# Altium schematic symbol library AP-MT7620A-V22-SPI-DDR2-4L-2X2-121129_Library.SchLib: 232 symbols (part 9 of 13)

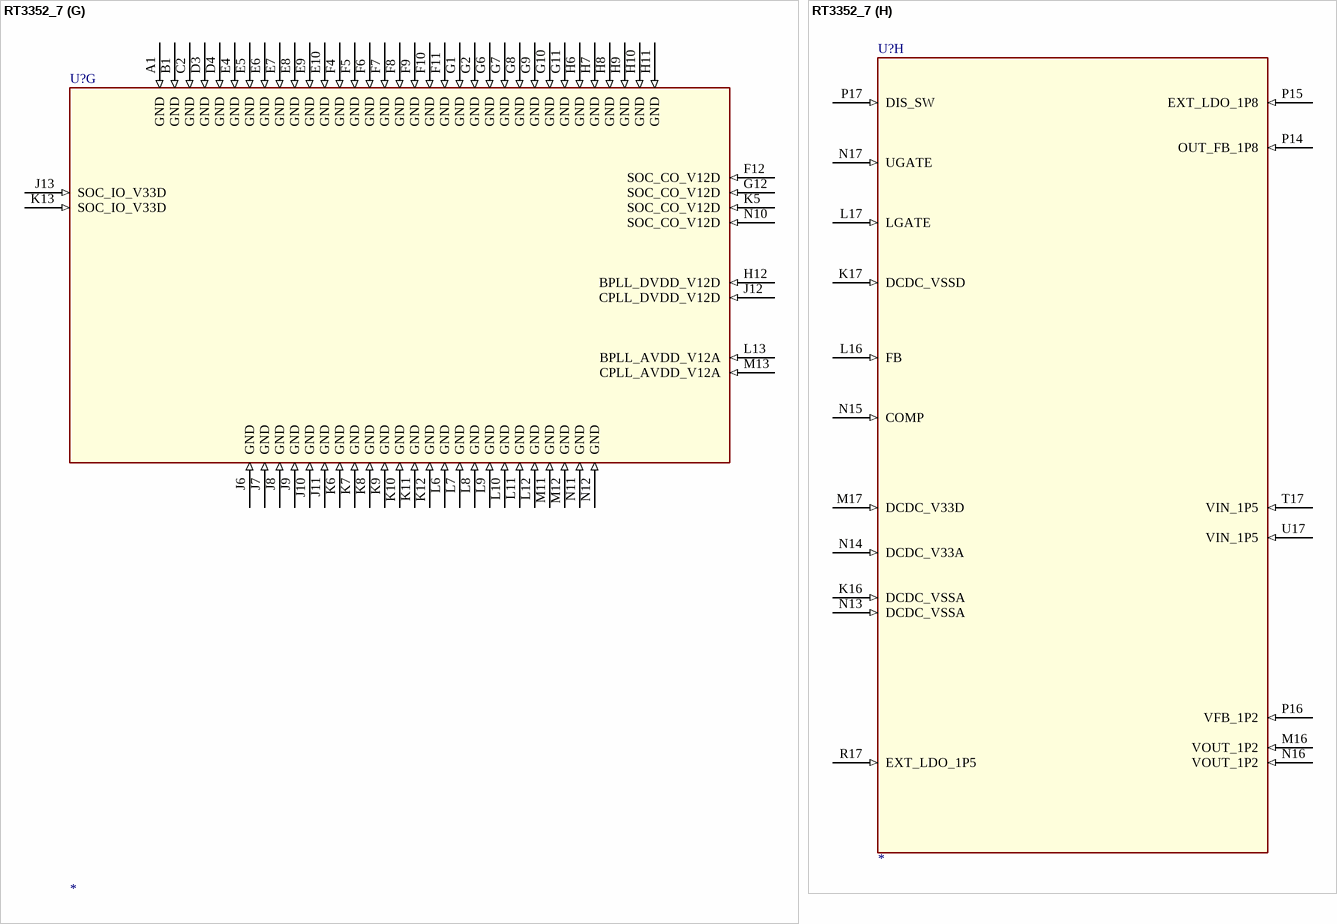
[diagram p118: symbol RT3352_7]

## RT3352_7
designator U?
part A pins: A6 PLL_VC_CAP (in), A7 LDORF_OUT_V12 (out), A8 RF_BB2_V12A (in), A9 ADC_V12 (in), B6 BG_V33A (in), B7 LDORF_IN_VX (in), B8 PLL_X2 (out), B9 PLL_X1 (in), C3 RF0_V12A (in), C4 RF0_IF_V12A (in), C5 VCO_V12A (in), C6 LDOPLL_OUT_V12 (out), C7 BG_RES_12K (in), D5 PLL_V12A (in), D6 RF_BB1_V12A (in), E3 RF1_IF_V12A (in), F3 RF1_V12A (in)
part B pins: A2 RF0_PA_OUTN (out), A3 RF0_PA_OUTP (out), A4 RF0_2G_INN (in), A5 RF0_2G_INP (in), A10 LNA_PE_G1 (out), A11 ANT_TRNB (out), B2 RF0_PA_V33N (in), B3 RF0_PA_V33P (in), B4 RF0_PA1_V33A (in), B10 LNA_PE_G0 (out), B11 ANT_TRN (out), C1 RF1_2G_INP (in), C8 BASE_TRX_IP (io), C9 BASE_TRX_IN (io), C10 PA_PE_G1 (out), D1 RF1_2G_INN (in), D2 RF1_PA_V33A (in), D7 RF_TSSI_IN (in), D8 BASE_TRX_QP (io), D9 BASE_TRX_QN (io), D10 PA_PE_G0 (out), D13 WLAN_LED_N (out), E1 RF1_PA_OUTP (out), E2 RF1_PA_V33P (in), F1 RF1_PA_OUTN (out), F2 RF1_PA_V33N (in)
part C pins: H15 MD0 (io), H16 MD1 (io), H17 MD2 (io), J12 DDR_IOC_V12D (in), J13 DDR_IOC_V12D (in), J14 MD3 (io), J15 MDQM0 (io), J16 MDQS0 (io), J17 MD6 (io), K12 DDR_IO_V33D (in), K13 DDR_IO_V33D (in), K14 MD8 (io), K15 MD7 (io), K16 MD5 (io), K17 MD4 (io), L12 DDR_IOL_V33D (in), L13 DDR_IOL_V33D (in), L14 MD13 (io), L15 MD10 (io), L16 MD11 (io), L17 MD9 (io), M11 DDR_IO_V33D (in), M12 DDR_IOR_V09D (in), M13 MD15 (io), M14 MD12 (io), M15 MD14 (io), M16 MDQS1 (io), M17 MDQM1 (io), N8 DDR_IO_V33D (in), N9 DDR_IO_V33D (in), N10 DDR_IO_V33D (in), N11 DDR_IO_V33D (in), N12 DDR_IOR_V09D (in), N13 MA0 (io), N14 MA3 (io), N15 MA8 (io), N16 MA10 (io), N17 MA13 (io), P8 MD31 (io), P9 MDQS3 (io), P10 MD22 (io), P11 MDQM2 (io), P12 MD16 (io), P13 MODT (io), P14 MA6 (io), P15 MA4 (io), P16 MA5 (io), P17 MA12 (io), R8 MD30 (io), R9 MD27 (io), R10 MD23 (io), R11 MDQS2 (io), R12 MD17 (io), R13 MCKE (io), R14 MCAS_N (io), R15 MA2 (io), R16 MA7 (io), R17 MA11 (io), T8 MD29 (io), T9 MDQM3 (io), T10 MD24 (io), T11 MD20 (io), T12 MD18 (io), T13 MCK_N (io), T14 MRAS_N (io), T15 MBA0 (io), T16 MA1 (io), T17 MA9 (io), U8 MD28 (io), U9 MD25 (io), U10 MD26 (io), U11 MD21 (io), U12 MD19 (io), U13 MCK_P (io), U14 MWE_N (io), U15 MBA1 (io), U16 MBA2 (io), U17 MCS_N (io)
part D pins: ?? NC (io), A13 JTAG_TMS (in), A14 SPI_MISO (in), A15 SPI_CS0 (out), A16 TXD (out), A17 RTS_N (out), B13 JTAG_TCLK (in), B14 SPI_MOSI (out), B15 SPI_CLK (out), B16 DTR_N (out), B17 DCD_N (in), C12 GPIO0 (io), C13 JTAG_TRST_N (in), C14 SPI_CS1 (out), C15 DSR_N (in), C16 CTS_N (in), D12 JTAG_TDO (out), D14 RIN (in), D15 RXD (in), E12 JTAG_TDI (in), E13 PORST_N (in), G15 RXD2 (in), G16 TXD2 (out), G17 I2C_SCLK (io), H14 I2C_SD (out)
part E pins: C17 UPHY1_PADP (io), D16 UPHY1_ID (io), D17 UPHY1_PADM (io), E14 UPHY_VDDL_V12D (in), E15 UPHY1_VBUS (io), E16 UPHY1_VRES (io), E17 UPHY0_PADP (io), F14 UPHY_VDDA_V33A (in), F15 UPHY0_VBUS (io), F16 UPHY0_VRES (io), F17 UPHY0_PADM (io), G14 UPHY0_ID (io)
part F pins: A12 EPHY_LED1_N (out), B12 EPHY_LED0_N (out), C11 EPHY_LED4_N (out), D11 EPHY_LED3_N (out), E11 EPHY_LED2_N (out), H3 MDC (out), H4 GE1_RXD0 (in), J3 MDIO (io), J4 GE1_RXDV (in), K3 GE1_RXD1 (in), K4 GE1_RXCLK (io), L3 GE1_RXD2 (in), L4 GE1_RXD3 (in), M3 GE1_TXD2 (out), M4 GE1_TXD3 (out), N3 GE1_TXD1 (out), N4 GE1_TXCLK (io), P3 GE1_TXD0 (out), P4 GE1_TXEN (out), P5 EPHY_V33A (in), P6 EPHY_V33A (in), P7 EPHY_V33A (in), R1 EPHY_REF_RES (io), R2 EPHY_TXN_p0 (out), R3 EPHY_RXN_p1 (in), R4 EPHY_RXN_p2 (in), R5 EPHY_RXP_p2 (in), R6 EPHY_RXP_p3 (in), R7 EPHY_RXN_p3 (in), T1 EPHY_RXN_p0 (in), T2 EPHY_TXP_p0 (out), T3 EPHY_RXP_p1 (in), T4 EPHY_TXN_p2 (out), T5 EPHY_TXN_p3 (out), T6 EPHY_RXN_p4 (in), T7 EPHY_TXN_p4 (out), U1 EPHY_RXP_p0 (in), U2 EPHY_TXP_p1 (out), U3 EPHY_TXN_p1 (out), U4 EPHY_TXP_p2 (out), U5 EPHY_TXP_p3 (out), U6 EPHY_RXP_p4 (in), U7 EPHY_TXP_p4 (out)
part G pins: A1 GND (in), B1 GND (in), C2 GND (in), D3 GND (in), D4 GND (in), E4 GND (in), E5 GND (in), E6 GND (in), E7 GND (in), E8 GND (in), E9 GND (in), E10 GND (in), F4 GND (in), F5 GND (in), F6 GND (in), F7 GND (in), F8 GND (in), F9 GND (in), F10 GND (in), F11 GND (in), F12 SOC_CO_V12D (in), G1 GND (in), G2 GND (in), G6 GND (in), G7 GND (in), G8 GND (in), G9 GND (in), G10 GND (in), G11 GND (in), G12 SOC_CO_V12D (in), H6 GND (in), H7 GND (in), H8 GND (in), H9 GND (in), H10 GND (in), H11 GND (in), H12 BPLL_DVDD_V12D (in), J6 GND (in), J7 GND (in), J8 GND (in), J9 GND (in), J10 GND (in), J11 GND (in), J12 CPLL_DVDD_V12D (in), J13 SOC_IO_V33D (in), K5 SOC_CO_V12D (in), K6 GND (in), K7 GND (in), K8 GND (in), K9 GND (in), K10 GND (in), K11 GND (in), K12 GND (in), K13 SOC_IO_V33D (in), L6 GND (in), L7 GND (in), L8 GND (in), L9 GND (in), L10 GND (in), L11 GND (in), L12 GND (in), L13 BPLL_AVDD_V12A (in), M11 GND (in), M12 GND (in), M13 CPLL_AVDD_V12A (in), N10 SOC_CO_V12D (in), N11 GND (in), N12 GND (in)
part H pins: K16 DCDC_VSSA (in), K17 DCDC_VSSD (in), L16 FB (in), L17 LGATE (in), M16 VOUT_1P2 (in), M17 DCDC_V33D (in), N13 DCDC_VSSA (in), N14 DCDC_V33A (in), N15 COMP (in), N16 VOUT_1P2 (in), N17 UGATE (in), P14 OUT_FB_1P8 (in), P15 EXT_LDO_1P8 (in), P16 VFB_1P2 (in), P17 DIS_SW (in), R17 EXT_LDO_1P5 (in), T17 VIN_1P5 (in), U17 VIN_1P5 (in)

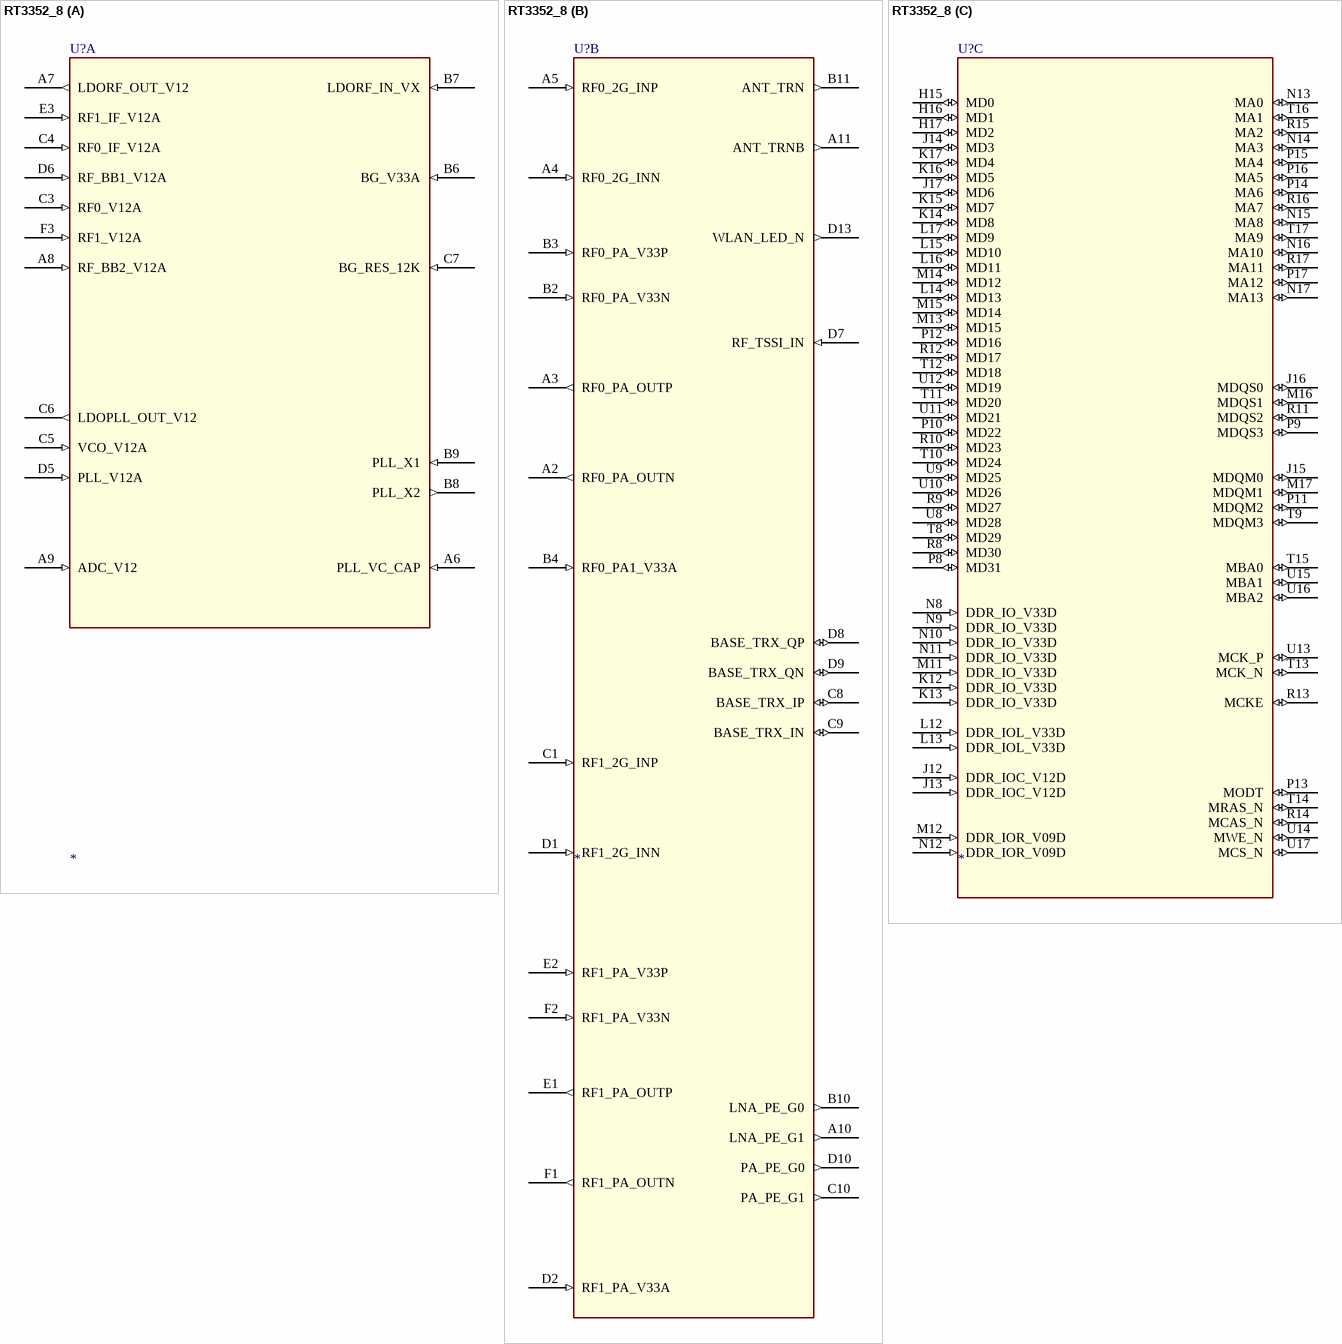
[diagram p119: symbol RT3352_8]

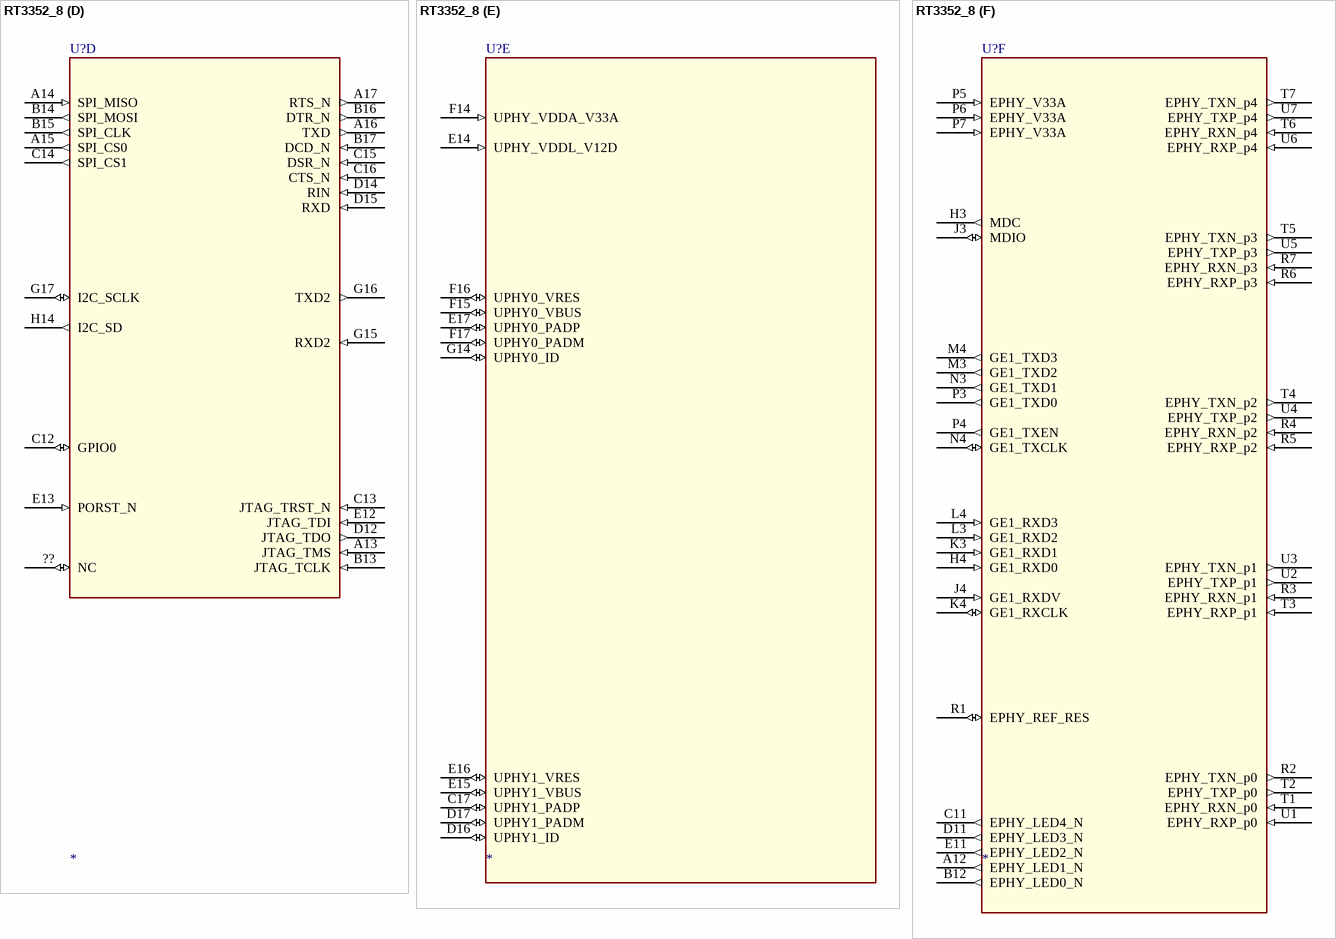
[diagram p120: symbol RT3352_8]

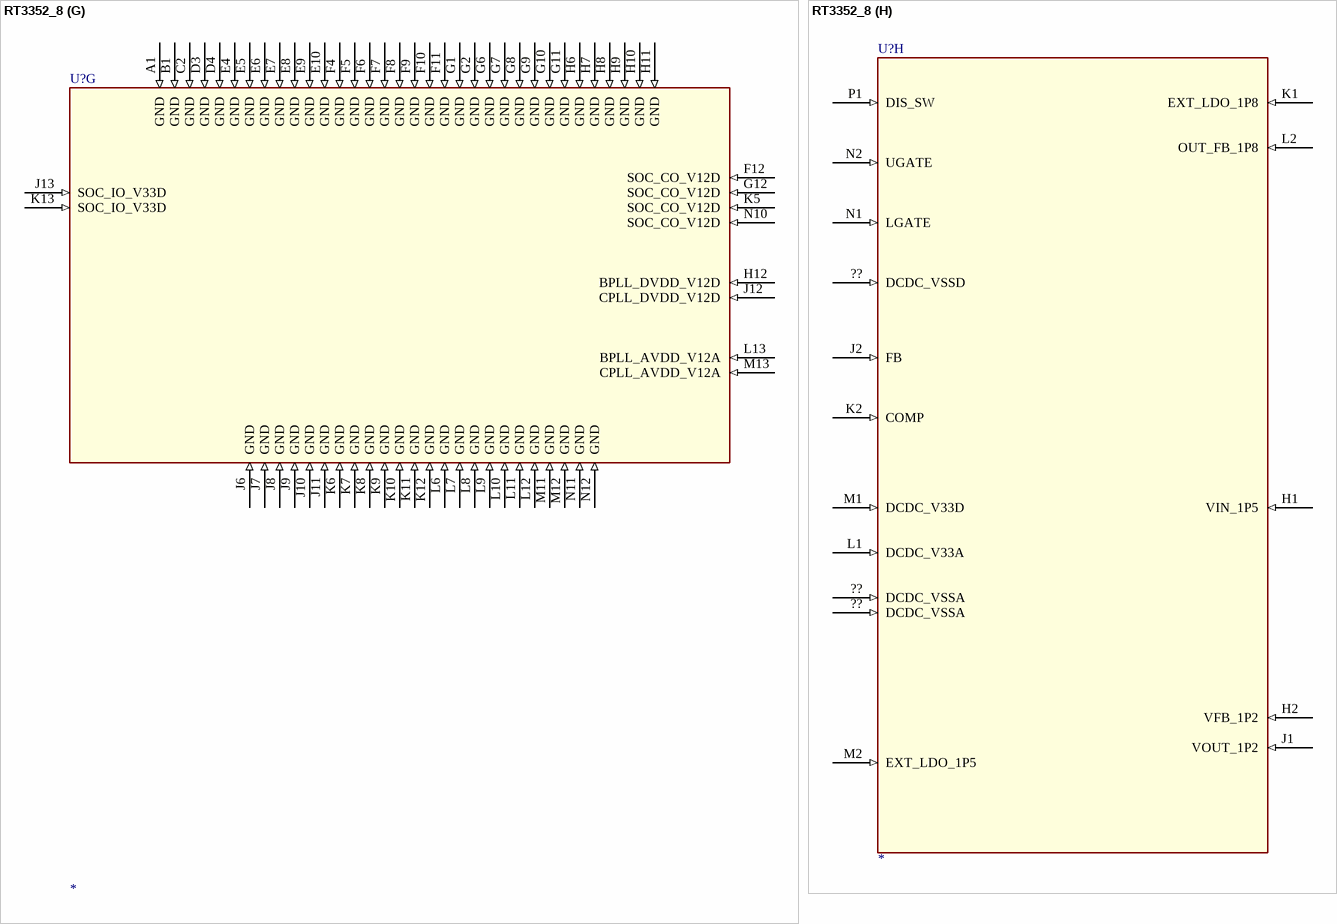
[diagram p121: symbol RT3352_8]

## RT3352_8
designator U?
part A pins: A6 PLL_VC_CAP (in), A7 LDORF_OUT_V12 (out), A8 RF_BB2_V12A (in), A9 ADC_V12 (in), B6 BG_V33A (in), B7 LDORF_IN_VX (in), B8 PLL_X2 (out), B9 PLL_X1 (in), C3 RF0_V12A (in), C4 RF0_IF_V12A (in), C5 VCO_V12A (in), C6 LDOPLL_OUT_V12 (out), C7 BG_RES_12K (in), D5 PLL_V12A (in), D6 RF_BB1_V12A (in), E3 RF1_IF_V12A (in), F3 RF1_V12A (in)
part B pins: A2 RF0_PA_OUTN (out), A3 RF0_PA_OUTP (out), A4 RF0_2G_INN (in), A5 RF0_2G_INP (in), A10 LNA_PE_G1 (out), A11 ANT_TRNB (out), B2 RF0_PA_V33N (in), B3 RF0_PA_V33P (in), B4 RF0_PA1_V33A (in), B10 LNA_PE_G0 (out), B11 ANT_TRN (out), C1 RF1_2G_INP (in), C8 BASE_TRX_IP (io), C9 BASE_TRX_IN (io), C10 PA_PE_G1 (out), D1 RF1_2G_INN (in), D2 RF1_PA_V33A (in), D7 RF_TSSI_IN (in), D8 BASE_TRX_QP (io), D9 BASE_TRX_QN (io), D10 PA_PE_G0 (out), D13 WLAN_LED_N (out), E1 RF1_PA_OUTP (out), E2 RF1_PA_V33P (in), F1 RF1_PA_OUTN (out), F2 RF1_PA_V33N (in)
part C pins: H15 MD0 (io), H16 MD1 (io), H17 MD2 (io), J12 DDR_IOC_V12D (in), J13 DDR_IOC_V12D (in), J14 MD3 (io), J15 MDQM0 (io), J16 MDQS0 (io), J17 MD6 (io), K12 DDR_IO_V33D (in), K13 DDR_IO_V33D (in), K14 MD8 (io), K15 MD7 (io), K16 MD5 (io), K17 MD4 (io), L12 DDR_IOL_V33D (in), L13 DDR_IOL_V33D (in), L14 MD13 (io), L15 MD10 (io), L16 MD11 (io), L17 MD9 (io), M11 DDR_IO_V33D (in), M12 DDR_IOR_V09D (in), M13 MD15 (io), M14 MD12 (io), M15 MD14 (io), M16 MDQS1 (io), M17 MDQM1 (io), N8 DDR_IO_V33D (in), N9 DDR_IO_V33D (in), N10 DDR_IO_V33D (in), N11 DDR_IO_V33D (in), N12 DDR_IOR_V09D (in), N13 MA0 (io), N14 MA3 (io), N15 MA8 (io), N16 MA10 (io), N17 MA13 (io), P8 MD31 (io), P9 MDQS3 (io), P10 MD22 (io), P11 MDQM2 (io), P12 MD16 (io), P13 MODT (io), P14 MA6 (io), P15 MA4 (io), P16 MA5 (io), P17 MA12 (io), R8 MD30 (io), R9 MD27 (io), R10 MD23 (io), R11 MDQS2 (io), R12 MD17 (io), R13 MCKE (io), R14 MCAS_N (io), R15 MA2 (io), R16 MA7 (io), R17 MA11 (io), T8 MD29 (io), T9 MDQM3 (io), T10 MD24 (io), T11 MD20 (io), T12 MD18 (io), T13 MCK_N (io), T14 MRAS_N (io), T15 MBA0 (io), T16 MA1 (io), T17 MA9 (io), U8 MD28 (io), U9 MD25 (io), U10 MD26 (io), U11 MD21 (io), U12 MD19 (io), U13 MCK_P (io), U14 MWE_N (io), U15 MBA1 (io), U16 MBA2 (io), U17 MCS_N (io)
part D pins: ?? NC (io), A13 JTAG_TMS (in), A14 SPI_MISO (in), A15 SPI_CS0 (out), A16 TXD (out), A17 RTS_N (out), B13 JTAG_TCLK (in), B14 SPI_MOSI (out), B15 SPI_CLK (out), B16 DTR_N (out), B17 DCD_N (in), C12 GPIO0 (io), C13 JTAG_TRST_N (in), C14 SPI_CS1 (out), C15 DSR_N (in), C16 CTS_N (in), D12 JTAG_TDO (out), D14 RIN (in), D15 RXD (in), E12 JTAG_TDI (in), E13 PORST_N (in), G15 RXD2 (in), G16 TXD2 (out), G17 I2C_SCLK (io), H14 I2C_SD (out)
part E pins: C17 UPHY1_PADP (io), D16 UPHY1_ID (io), D17 UPHY1_PADM (io), E14 UPHY_VDDL_V12D (in), E15 UPHY1_VBUS (io), E16 UPHY1_VRES (io), E17 UPHY0_PADP (io), F14 UPHY_VDDA_V33A (in), F15 UPHY0_VBUS (io), F16 UPHY0_VRES (io), F17 UPHY0_PADM (io), G14 UPHY0_ID (io)
part F pins: A12 EPHY_LED1_N (out), B12 EPHY_LED0_N (out), C11 EPHY_LED4_N (out), D11 EPHY_LED3_N (out), E11 EPHY_LED2_N (out), H3 MDC (out), H4 GE1_RXD0 (in), J3 MDIO (io), J4 GE1_RXDV (in), K3 GE1_RXD1 (in), K4 GE1_RXCLK (io), L3 GE1_RXD2 (in), L4 GE1_RXD3 (in), M3 GE1_TXD2 (out), M4 GE1_TXD3 (out), N3 GE1_TXD1 (out), N4 GE1_TXCLK (io), P3 GE1_TXD0 (out), P4 GE1_TXEN (out), P5 EPHY_V33A (in), P6 EPHY_V33A (in), P7 EPHY_V33A (in), R1 EPHY_REF_RES (io), R2 EPHY_TXN_p0 (out), R3 EPHY_RXN_p1 (in), R4 EPHY_RXN_p2 (in), R5 EPHY_RXP_p2 (in), R6 EPHY_RXP_p3 (in), R7 EPHY_RXN_p3 (in), T1 EPHY_RXN_p0 (in), T2 EPHY_TXP_p0 (out), T3 EPHY_RXP_p1 (in), T4 EPHY_TXN_p2 (out), T5 EPHY_TXN_p3 (out), T6 EPHY_RXN_p4 (in), T7 EPHY_TXN_p4 (out), U1 EPHY_RXP_p0 (in), U2 EPHY_TXP_p1 (out), U3 EPHY_TXN_p1 (out), U4 EPHY_TXP_p2 (out), U5 EPHY_TXP_p3 (out), U6 EPHY_RXP_p4 (in), U7 EPHY_TXP_p4 (out)
part G pins: A1 GND (in), B1 GND (in), C2 GND (in), D3 GND (in), D4 GND (in), E4 GND (in), E5 GND (in), E6 GND (in), E7 GND (in), E8 GND (in), E9 GND (in), E10 GND (in), F4 GND (in), F5 GND (in), F6 GND (in), F7 GND (in), F8 GND (in), F9 GND (in), F10 GND (in), F11 GND (in), F12 SOC_CO_V12D (in), G1 GND (in), G2 GND (in), G6 GND (in), G7 GND (in), G8 GND (in), G9 GND (in), G10 GND (in), G11 GND (in), G12 SOC_CO_V12D (in), H6 GND (in), H7 GND (in), H8 GND (in), H9 GND (in), H10 GND (in), H11 GND (in), H12 BPLL_DVDD_V12D (in), J6 GND (in), J7 GND (in), J8 GND (in), J9 GND (in), J10 GND (in), J11 GND (in), J12 CPLL_DVDD_V12D (in), J13 SOC_IO_V33D (in), K5 SOC_CO_V12D (in), K6 GND (in), K7 GND (in), K8 GND (in), K9 GND (in), K10 GND (in), K11 GND (in), K12 GND (in), K13 SOC_IO_V33D (in), L6 GND (in), L7 GND (in), L8 GND (in), L9 GND (in), L10 GND (in), L11 GND (in), L12 GND (in), L13 BPLL_AVDD_V12A (in), M11 GND (in), M12 GND (in), M13 CPLL_AVDD_V12A (in), N10 SOC_CO_V12D (in), N11 GND (in), N12 GND (in)
part H pins: ?? DCDC_VSSD (in), ?? DCDC_VSSA (in), ?? DCDC_VSSA (in), H1 VIN_1P5 (in), H2 VFB_1P2 (in), J1 VOUT_1P2 (in), J2 FB (in), K1 EXT_LDO_1P8 (in), K2 COMP (in), L1 DCDC_V33A (in), L2 OUT_FB_1P8 (in), M1 DCDC_V33D (in), M2 EXT_LDO_1P5 (in), N1 LGATE (in), N2 UGATE (in), P1 DIS_SW (in)

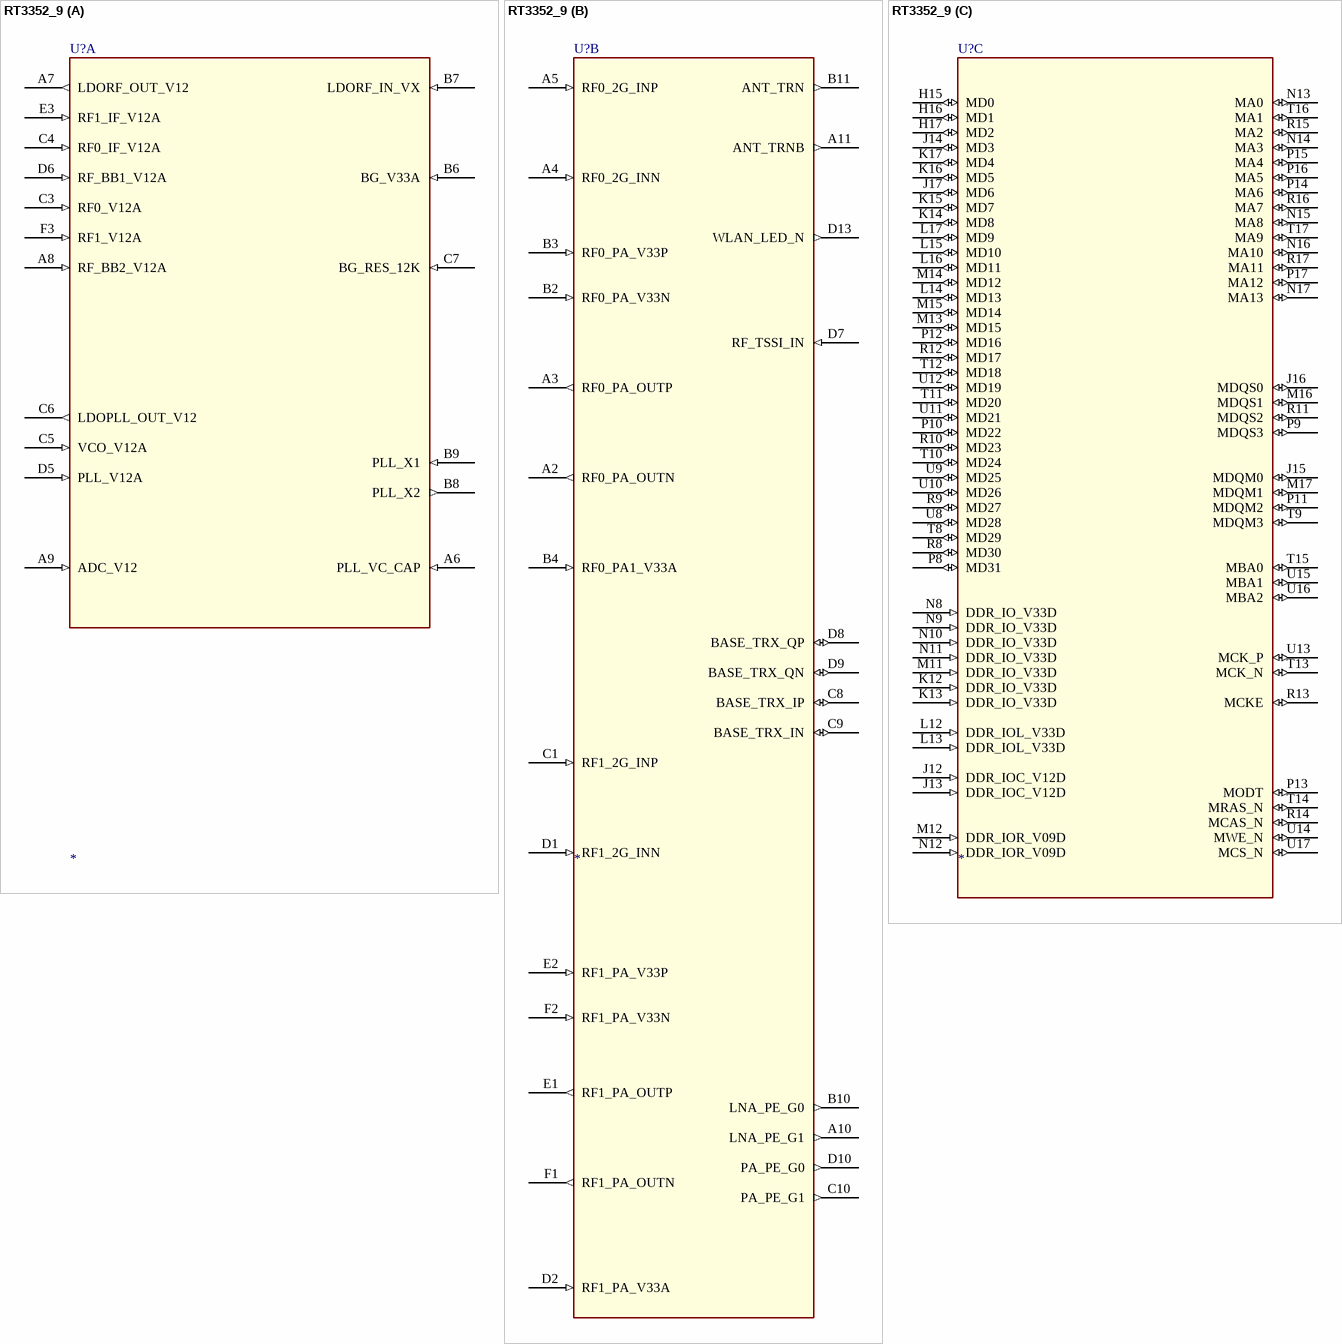
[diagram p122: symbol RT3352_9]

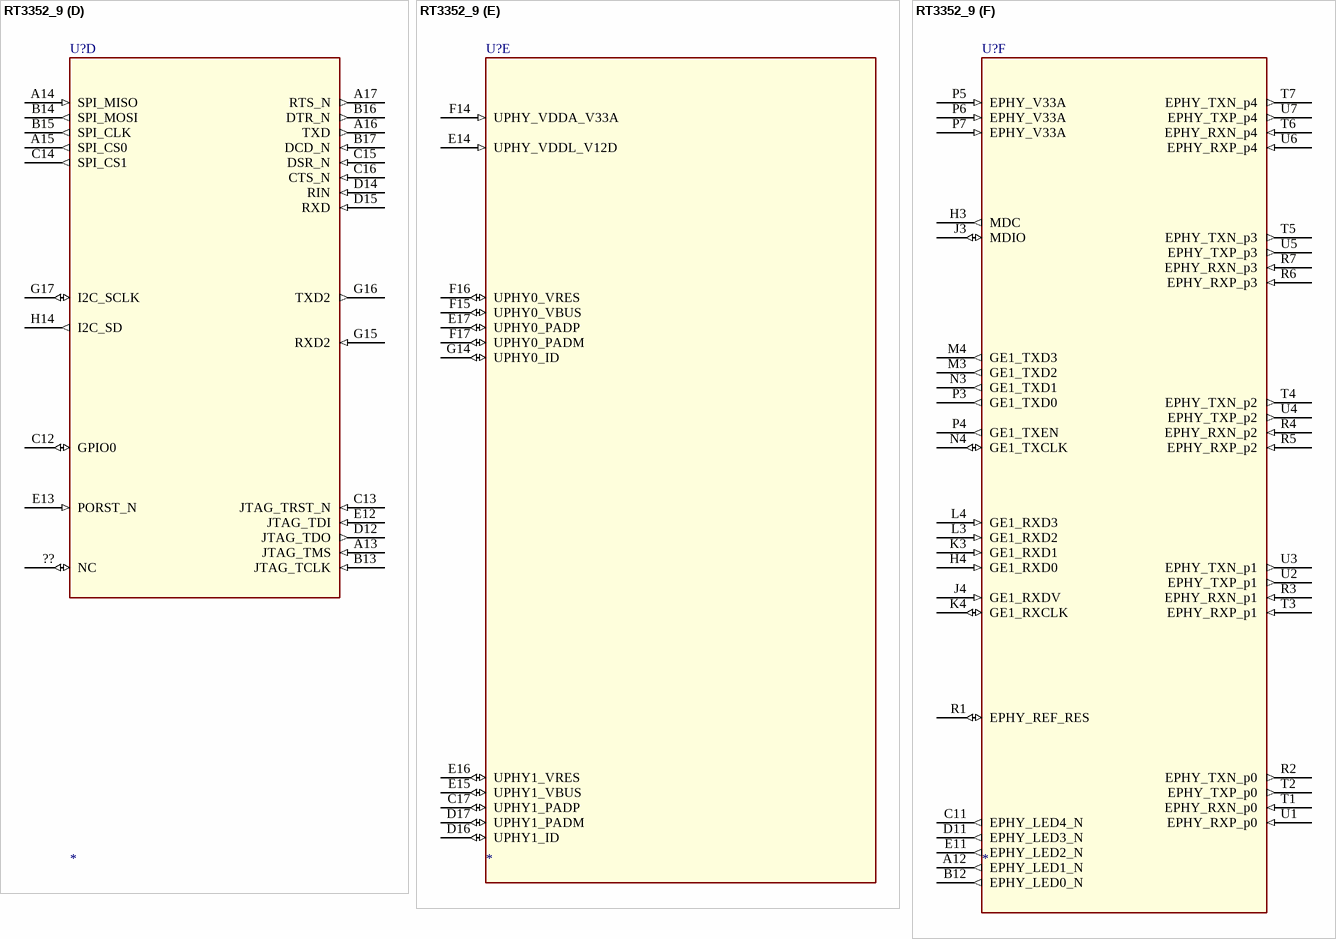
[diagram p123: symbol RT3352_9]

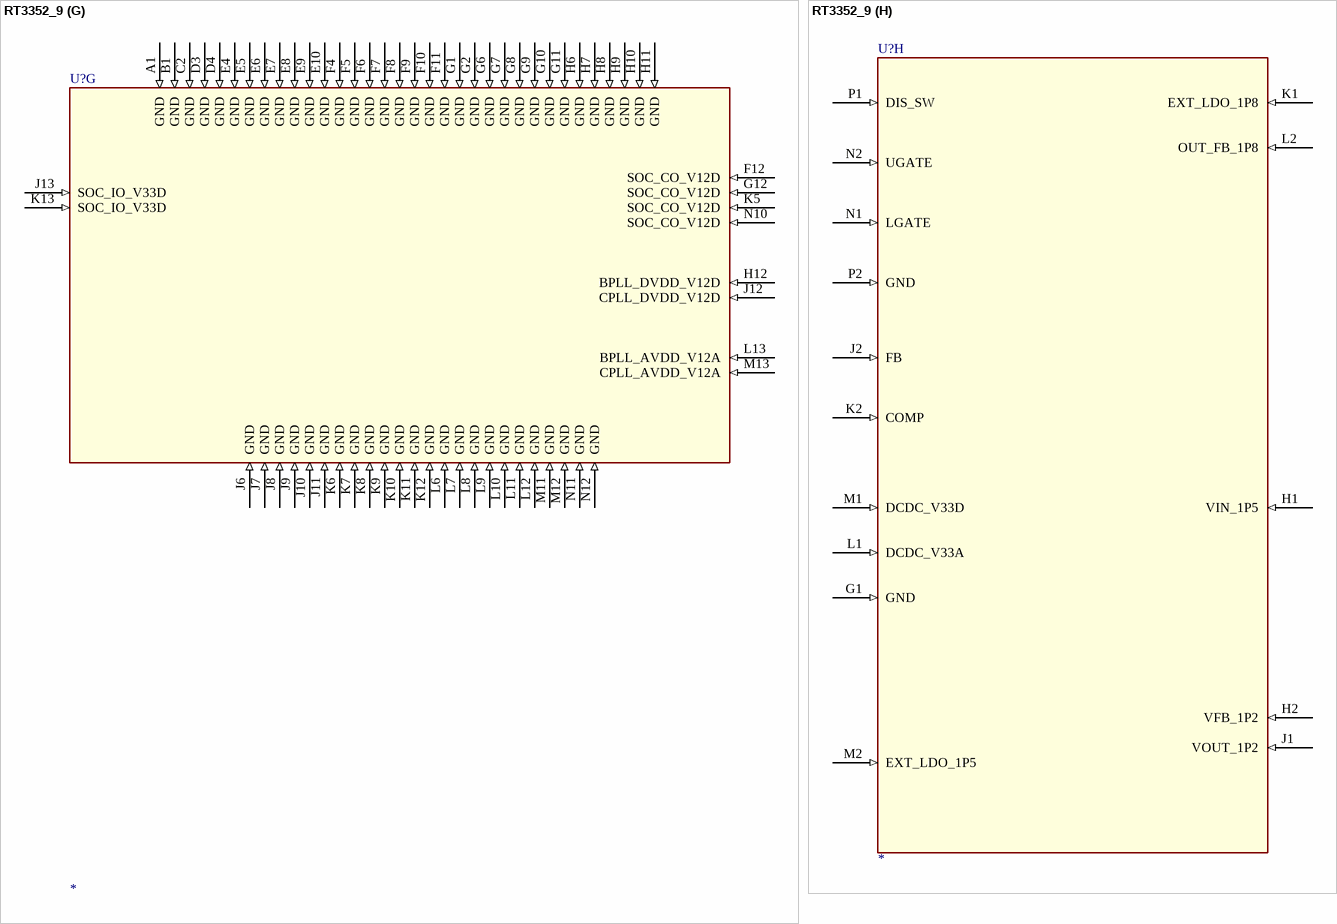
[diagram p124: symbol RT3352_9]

## RT3352_9
designator U?
part A pins: A6 PLL_VC_CAP (in), A7 LDORF_OUT_V12 (out), A8 RF_BB2_V12A (in), A9 ADC_V12 (in), B6 BG_V33A (in), B7 LDORF_IN_VX (in), B8 PLL_X2 (out), B9 PLL_X1 (in), C3 RF0_V12A (in), C4 RF0_IF_V12A (in), C5 VCO_V12A (in), C6 LDOPLL_OUT_V12 (out), C7 BG_RES_12K (in), D5 PLL_V12A (in), D6 RF_BB1_V12A (in), E3 RF1_IF_V12A (in), F3 RF1_V12A (in)
part B pins: A2 RF0_PA_OUTN (out), A3 RF0_PA_OUTP (out), A4 RF0_2G_INN (in), A5 RF0_2G_INP (in), A10 LNA_PE_G1 (out), A11 ANT_TRNB (out), B2 RF0_PA_V33N (in), B3 RF0_PA_V33P (in), B4 RF0_PA1_V33A (in), B10 LNA_PE_G0 (out), B11 ANT_TRN (out), C1 RF1_2G_INP (in), C8 BASE_TRX_IP (io), C9 BASE_TRX_IN (io), C10 PA_PE_G1 (out), D1 RF1_2G_INN (in), D2 RF1_PA_V33A (in), D7 RF_TSSI_IN (in), D8 BASE_TRX_QP (io), D9 BASE_TRX_QN (io), D10 PA_PE_G0 (out), D13 WLAN_LED_N (out), E1 RF1_PA_OUTP (out), E2 RF1_PA_V33P (in), F1 RF1_PA_OUTN (out), F2 RF1_PA_V33N (in)
part C pins: H15 MD0 (io), H16 MD1 (io), H17 MD2 (io), J12 DDR_IOC_V12D (in), J13 DDR_IOC_V12D (in), J14 MD3 (io), J15 MDQM0 (io), J16 MDQS0 (io), J17 MD6 (io), K12 DDR_IO_V33D (in), K13 DDR_IO_V33D (in), K14 MD8 (io), K15 MD7 (io), K16 MD5 (io), K17 MD4 (io), L12 DDR_IOL_V33D (in), L13 DDR_IOL_V33D (in), L14 MD13 (io), L15 MD10 (io), L16 MD11 (io), L17 MD9 (io), M11 DDR_IO_V33D (in), M12 DDR_IOR_V09D (in), M13 MD15 (io), M14 MD12 (io), M15 MD14 (io), M16 MDQS1 (io), M17 MDQM1 (io), N8 DDR_IO_V33D (in), N9 DDR_IO_V33D (in), N10 DDR_IO_V33D (in), N11 DDR_IO_V33D (in), N12 DDR_IOR_V09D (in), N13 MA0 (io), N14 MA3 (io), N15 MA8 (io), N16 MA10 (io), N17 MA13 (io), P8 MD31 (io), P9 MDQS3 (io), P10 MD22 (io), P11 MDQM2 (io), P12 MD16 (io), P13 MODT (io), P14 MA6 (io), P15 MA4 (io), P16 MA5 (io), P17 MA12 (io), R8 MD30 (io), R9 MD27 (io), R10 MD23 (io), R11 MDQS2 (io), R12 MD17 (io), R13 MCKE (io), R14 MCAS_N (io), R15 MA2 (io), R16 MA7 (io), R17 MA11 (io), T8 MD29 (io), T9 MDQM3 (io), T10 MD24 (io), T11 MD20 (io), T12 MD18 (io), T13 MCK_N (io), T14 MRAS_N (io), T15 MBA0 (io), T16 MA1 (io), T17 MA9 (io), U8 MD28 (io), U9 MD25 (io), U10 MD26 (io), U11 MD21 (io), U12 MD19 (io), U13 MCK_P (io), U14 MWE_N (io), U15 MBA1 (io), U16 MBA2 (io), U17 MCS_N (io)
part D pins: ?? NC (io), A13 JTAG_TMS (in), A14 SPI_MISO (in), A15 SPI_CS0 (out), A16 TXD (out), A17 RTS_N (out), B13 JTAG_TCLK (in), B14 SPI_MOSI (out), B15 SPI_CLK (out), B16 DTR_N (out), B17 DCD_N (in), C12 GPIO0 (io), C13 JTAG_TRST_N (in), C14 SPI_CS1 (out), C15 DSR_N (in), C16 CTS_N (in), D12 JTAG_TDO (out), D14 RIN (in), D15 RXD (in), E12 JTAG_TDI (in), E13 PORST_N (in), G15 RXD2 (in), G16 TXD2 (out), G17 I2C_SCLK (io), H14 I2C_SD (out)
part E pins: C17 UPHY1_PADP (io), D16 UPHY1_ID (io), D17 UPHY1_PADM (io), E14 UPHY_VDDL_V12D (in), E15 UPHY1_VBUS (io), E16 UPHY1_VRES (io), E17 UPHY0_PADP (io), F14 UPHY_VDDA_V33A (in), F15 UPHY0_VBUS (io), F16 UPHY0_VRES (io), F17 UPHY0_PADM (io), G14 UPHY0_ID (io)
part F pins: A12 EPHY_LED1_N (out), B12 EPHY_LED0_N (out), C11 EPHY_LED4_N (out), D11 EPHY_LED3_N (out), E11 EPHY_LED2_N (out), H3 MDC (out), H4 GE1_RXD0 (in), J3 MDIO (io), J4 GE1_RXDV (in), K3 GE1_RXD1 (in), K4 GE1_RXCLK (io), L3 GE1_RXD2 (in), L4 GE1_RXD3 (in), M3 GE1_TXD2 (out), M4 GE1_TXD3 (out), N3 GE1_TXD1 (out), N4 GE1_TXCLK (io), P3 GE1_TXD0 (out), P4 GE1_TXEN (out), P5 EPHY_V33A (in), P6 EPHY_V33A (in), P7 EPHY_V33A (in), R1 EPHY_REF_RES (io), R2 EPHY_TXN_p0 (out), R3 EPHY_RXN_p1 (in), R4 EPHY_RXN_p2 (in), R5 EPHY_RXP_p2 (in), R6 EPHY_RXP_p3 (in), R7 EPHY_RXN_p3 (in), T1 EPHY_RXN_p0 (in), T2 EPHY_TXP_p0 (out), T3 EPHY_RXP_p1 (in), T4 EPHY_TXN_p2 (out), T5 EPHY_TXN_p3 (out), T6 EPHY_RXN_p4 (in), T7 EPHY_TXN_p4 (out), U1 EPHY_RXP_p0 (in), U2 EPHY_TXP_p1 (out), U3 EPHY_TXN_p1 (out), U4 EPHY_TXP_p2 (out), U5 EPHY_TXP_p3 (out), U6 EPHY_RXP_p4 (in), U7 EPHY_TXP_p4 (out)
part G pins: A1 GND (in), B1 GND (in), C2 GND (in), D3 GND (in), D4 GND (in), E4 GND (in), E5 GND (in), E6 GND (in), E7 GND (in), E8 GND (in), E9 GND (in), E10 GND (in), F4 GND (in), F5 GND (in), F6 GND (in), F7 GND (in), F8 GND (in), F9 GND (in), F10 GND (in), F11 GND (in), F12 SOC_CO_V12D (in), G1 GND (in), G2 GND (in), G6 GND (in), G7 GND (in), G8 GND (in), G9 GND (in), G10 GND (in), G11 GND (in), G12 SOC_CO_V12D (in), H6 GND (in), H7 GND (in), H8 GND (in), H9 GND (in), H10 GND (in), H11 GND (in), H12 BPLL_DVDD_V12D (in), J6 GND (in), J7 GND (in), J8 GND (in), J9 GND (in), J10 GND (in), J11 GND (in), J12 CPLL_DVDD_V12D (in), J13 SOC_IO_V33D (in), K5 SOC_CO_V12D (in), K6 GND (in), K7 GND (in), K8 GND (in), K9 GND (in), K10 GND (in), K11 GND (in), K12 GND (in), K13 SOC_IO_V33D (in), L6 GND (in), L7 GND (in), L8 GND (in), L9 GND (in), L10 GND (in), L11 GND (in), L12 GND (in), L13 BPLL_AVDD_V12A (in), M11 GND (in), M12 GND (in), M13 CPLL_AVDD_V12A (in), N10 SOC_CO_V12D (in), N11 GND (in), N12 GND (in)
part H pins: G1 GND (in), H1 VIN_1P5 (in), H2 VFB_1P2 (in), J1 VOUT_1P2 (in), J2 FB (in), K1 EXT_LDO_1P8 (in), K2 COMP (in), L1 DCDC_V33A (in), L2 OUT_FB_1P8 (in), M1 DCDC_V33D (in), M2 EXT_LDO_1P5 (in), N1 LGATE (in), N2 UGATE (in), P1 DIS_SW (in), P2 GND (in)

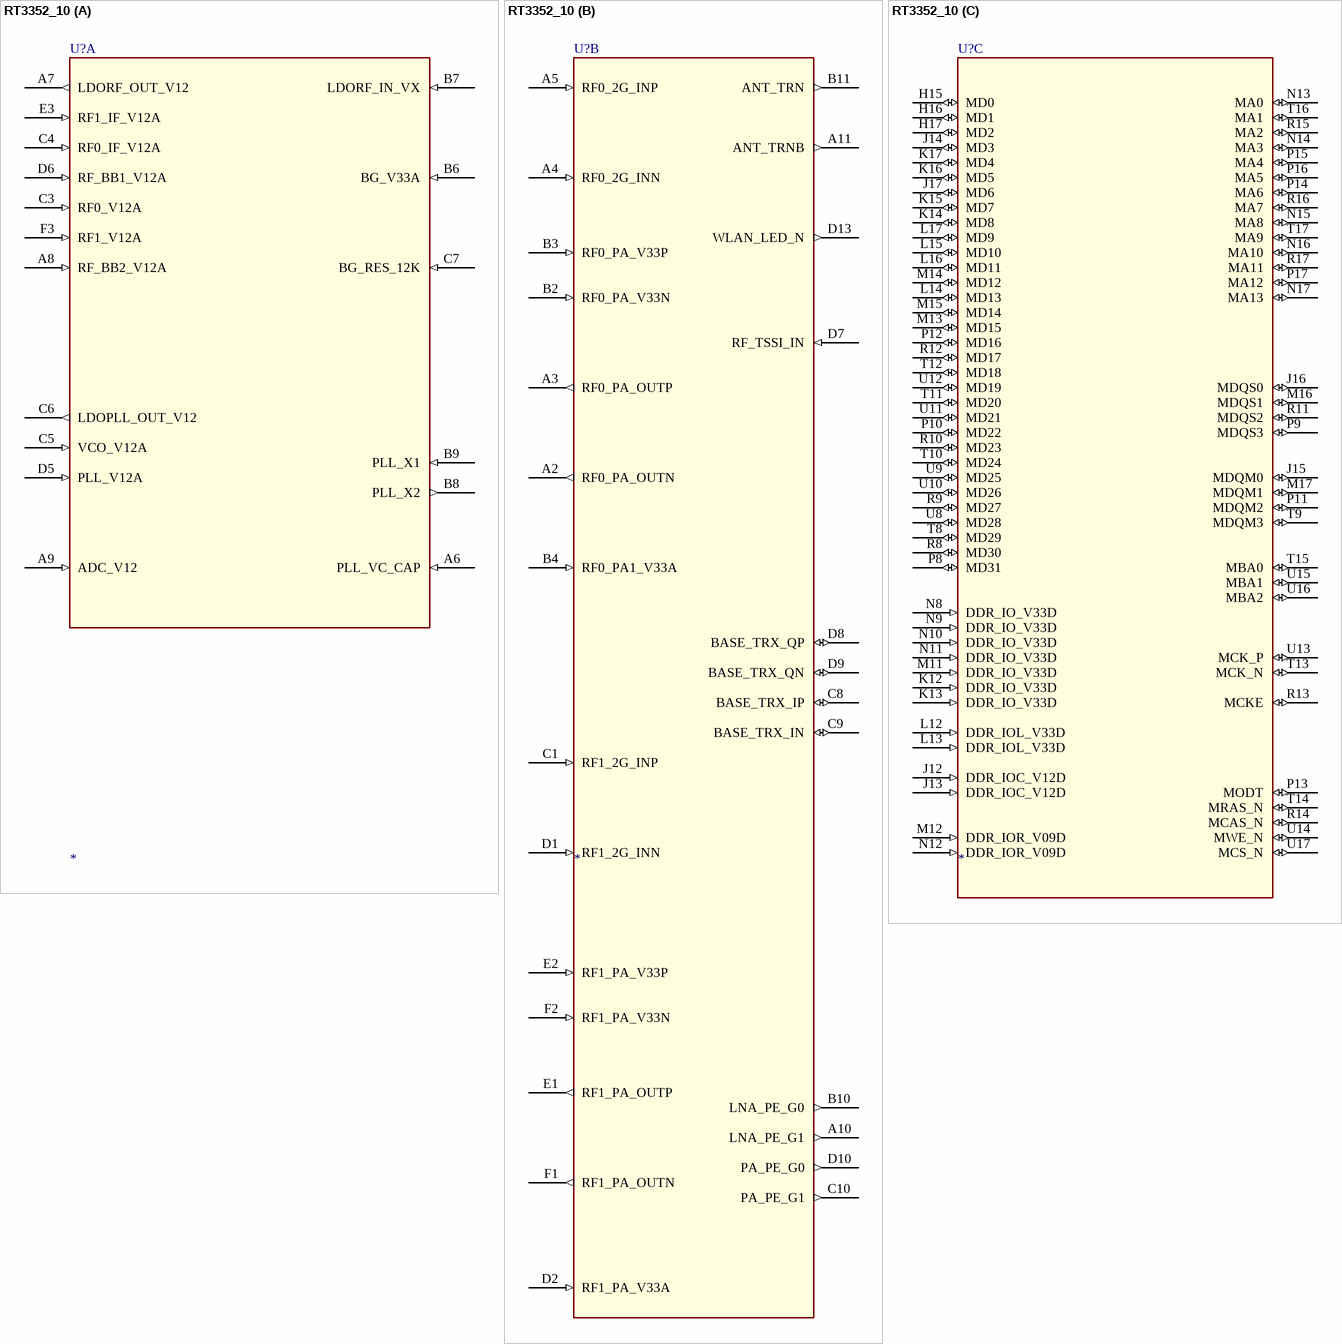
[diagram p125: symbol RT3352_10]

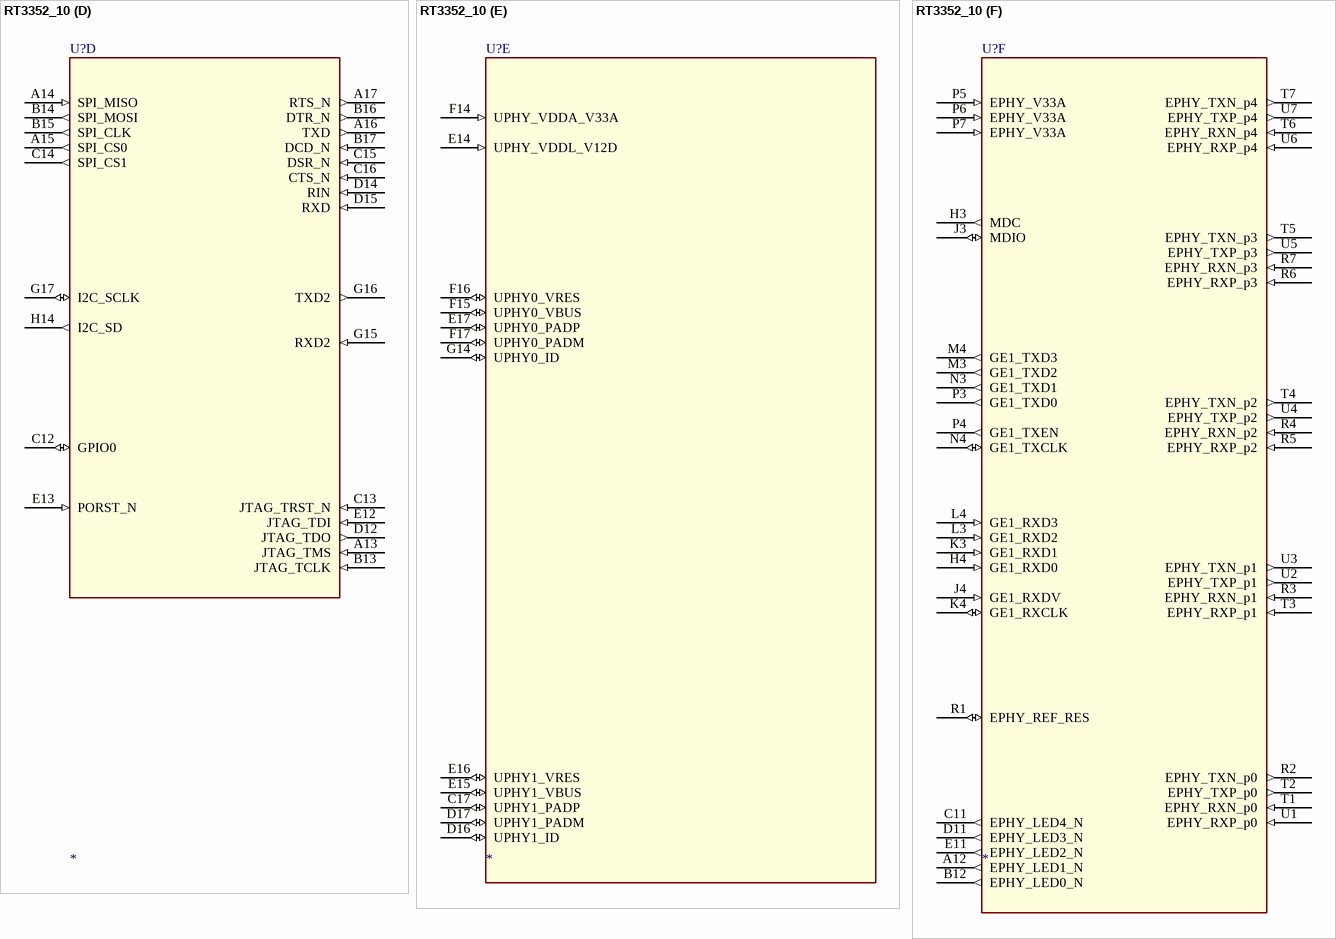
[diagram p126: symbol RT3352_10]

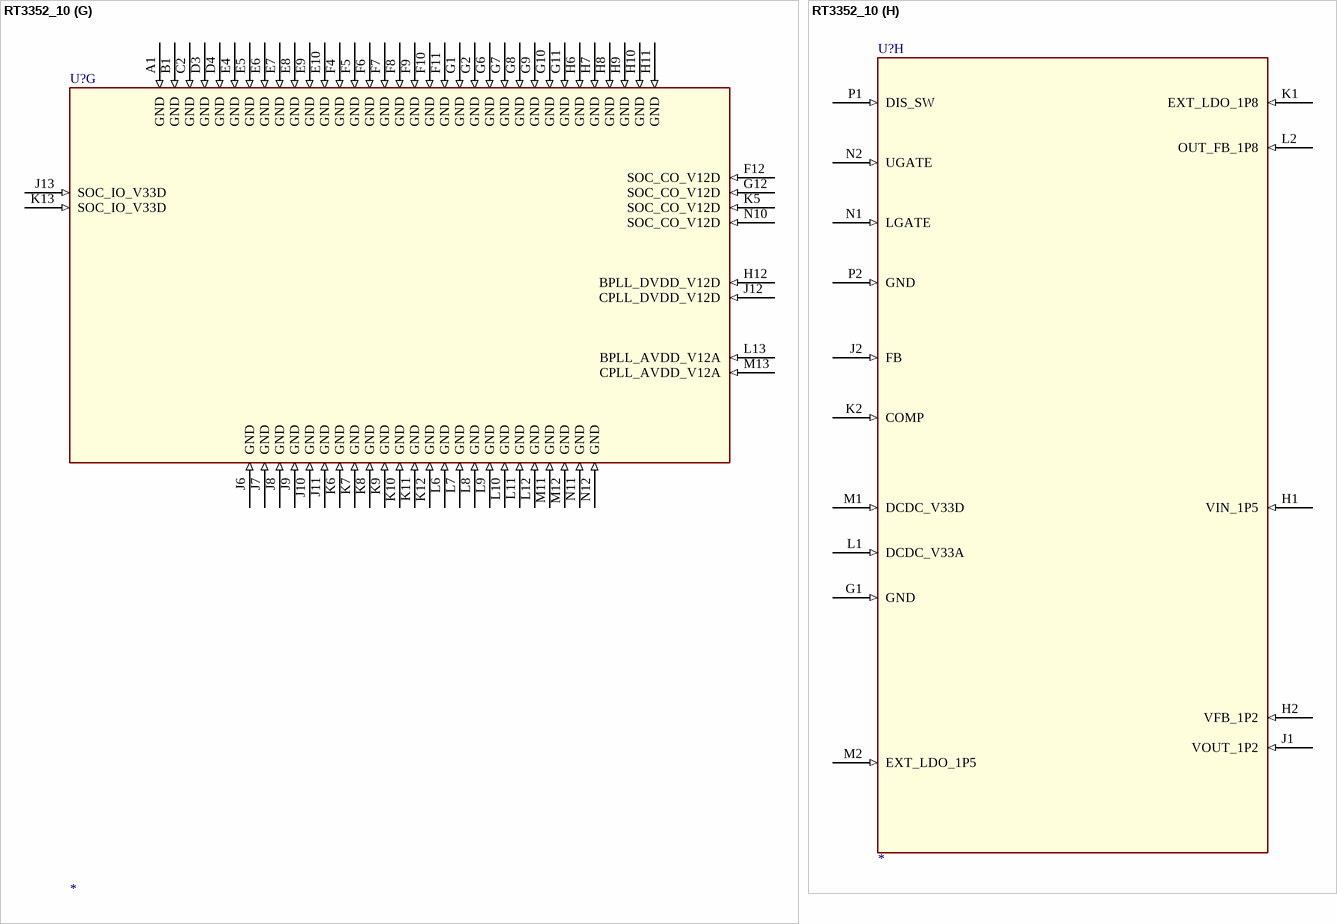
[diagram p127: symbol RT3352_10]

## RT3352_10
designator U?
part A pins: A6 PLL_VC_CAP (in), A7 LDORF_OUT_V12 (out), A8 RF_BB2_V12A (in), A9 ADC_V12 (in), B6 BG_V33A (in), B7 LDORF_IN_VX (in), B8 PLL_X2 (out), B9 PLL_X1 (in), C3 RF0_V12A (in), C4 RF0_IF_V12A (in), C5 VCO_V12A (in), C6 LDOPLL_OUT_V12 (out), C7 BG_RES_12K (in), D5 PLL_V12A (in), D6 RF_BB1_V12A (in), E3 RF1_IF_V12A (in), F3 RF1_V12A (in)
part B pins: A2 RF0_PA_OUTN (out), A3 RF0_PA_OUTP (out), A4 RF0_2G_INN (in), A5 RF0_2G_INP (in), A10 LNA_PE_G1 (out), A11 ANT_TRNB (out), B2 RF0_PA_V33N (in), B3 RF0_PA_V33P (in), B4 RF0_PA1_V33A (in), B10 LNA_PE_G0 (out), B11 ANT_TRN (out), C1 RF1_2G_INP (in), C8 BASE_TRX_IP (io), C9 BASE_TRX_IN (io), C10 PA_PE_G1 (out), D1 RF1_2G_INN (in), D2 RF1_PA_V33A (in), D7 RF_TSSI_IN (in), D8 BASE_TRX_QP (io), D9 BASE_TRX_QN (io), D10 PA_PE_G0 (out), D13 WLAN_LED_N (out), E1 RF1_PA_OUTP (out), E2 RF1_PA_V33P (in), F1 RF1_PA_OUTN (out), F2 RF1_PA_V33N (in)
part C pins: H15 MD0 (io), H16 MD1 (io), H17 MD2 (io), J12 DDR_IOC_V12D (in), J13 DDR_IOC_V12D (in), J14 MD3 (io), J15 MDQM0 (io), J16 MDQS0 (io), J17 MD6 (io), K12 DDR_IO_V33D (in), K13 DDR_IO_V33D (in), K14 MD8 (io), K15 MD7 (io), K16 MD5 (io), K17 MD4 (io), L12 DDR_IOL_V33D (in), L13 DDR_IOL_V33D (in), L14 MD13 (io), L15 MD10 (io), L16 MD11 (io), L17 MD9 (io), M11 DDR_IO_V33D (in), M12 DDR_IOR_V09D (in), M13 MD15 (io), M14 MD12 (io), M15 MD14 (io), M16 MDQS1 (io), M17 MDQM1 (io), N8 DDR_IO_V33D (in), N9 DDR_IO_V33D (in), N10 DDR_IO_V33D (in), N11 DDR_IO_V33D (in), N12 DDR_IOR_V09D (in), N13 MA0 (io), N14 MA3 (io), N15 MA8 (io), N16 MA10 (io), N17 MA13 (io), P8 MD31 (io), P9 MDQS3 (io), P10 MD22 (io), P11 MDQM2 (io), P12 MD16 (io), P13 MODT (io), P14 MA6 (io), P15 MA4 (io), P16 MA5 (io), P17 MA12 (io), R8 MD30 (io), R9 MD27 (io), R10 MD23 (io), R11 MDQS2 (io), R12 MD17 (io), R13 MCKE (io), R14 MCAS_N (io), R15 MA2 (io), R16 MA7 (io), R17 MA11 (io), T8 MD29 (io), T9 MDQM3 (io), T10 MD24 (io), T11 MD20 (io), T12 MD18 (io), T13 MCK_N (io), T14 MRAS_N (io), T15 MBA0 (io), T16 MA1 (io), T17 MA9 (io), U8 MD28 (io), U9 MD25 (io), U10 MD26 (io), U11 MD21 (io), U12 MD19 (io), U13 MCK_P (io), U14 MWE_N (io), U15 MBA1 (io), U16 MBA2 (io), U17 MCS_N (io)
part D pins: A13 JTAG_TMS (in), A14 SPI_MISO (in), A15 SPI_CS0 (out), A16 TXD (out), A17 RTS_N (out), B13 JTAG_TCLK (in), B14 SPI_MOSI (out), B15 SPI_CLK (out), B16 DTR_N (out), B17 DCD_N (in), C12 GPIO0 (io), C13 JTAG_TRST_N (in), C14 SPI_CS1 (out), C15 DSR_N (in), C16 CTS_N (in), D12 JTAG_TDO (out), D14 RIN (in), D15 RXD (in), E12 JTAG_TDI (in), E13 PORST_N (in), G15 RXD2 (in), G16 TXD2 (out), G17 I2C_SCLK (io), H14 I2C_SD (out)
part E pins: C17 UPHY1_PADP (io), D16 UPHY1_ID (io), D17 UPHY1_PADM (io), E14 UPHY_VDDL_V12D (in), E15 UPHY1_VBUS (io), E16 UPHY1_VRES (io), E17 UPHY0_PADP (io), F14 UPHY_VDDA_V33A (in), F15 UPHY0_VBUS (io), F16 UPHY0_VRES (io), F17 UPHY0_PADM (io), G14 UPHY0_ID (io)
part F pins: A12 EPHY_LED1_N (out), B12 EPHY_LED0_N (out), C11 EPHY_LED4_N (out), D11 EPHY_LED3_N (out), E11 EPHY_LED2_N (out), H3 MDC (out), H4 GE1_RXD0 (in), J3 MDIO (io), J4 GE1_RXDV (in), K3 GE1_RXD1 (in), K4 GE1_RXCLK (io), L3 GE1_RXD2 (in), L4 GE1_RXD3 (in), M3 GE1_TXD2 (out), M4 GE1_TXD3 (out), N3 GE1_TXD1 (out), N4 GE1_TXCLK (io), P3 GE1_TXD0 (out), P4 GE1_TXEN (out), P5 EPHY_V33A (in), P6 EPHY_V33A (in), P7 EPHY_V33A (in), R1 EPHY_REF_RES (io), R2 EPHY_TXN_p0 (out), R3 EPHY_RXN_p1 (in), R4 EPHY_RXN_p2 (in), R5 EPHY_RXP_p2 (in), R6 EPHY_RXP_p3 (in), R7 EPHY_RXN_p3 (in), T1 EPHY_RXN_p0 (in), T2 EPHY_TXP_p0 (out), T3 EPHY_RXP_p1 (in), T4 EPHY_TXN_p2 (out), T5 EPHY_TXN_p3 (out), T6 EPHY_RXN_p4 (in), T7 EPHY_TXN_p4 (out), U1 EPHY_RXP_p0 (in), U2 EPHY_TXP_p1 (out), U3 EPHY_TXN_p1 (out), U4 EPHY_TXP_p2 (out), U5 EPHY_TXP_p3 (out), U6 EPHY_RXP_p4 (in), U7 EPHY_TXP_p4 (out)
part G pins: A1 GND (in), B1 GND (in), C2 GND (in), D3 GND (in), D4 GND (in), E4 GND (in), E5 GND (in), E6 GND (in), E7 GND (in), E8 GND (in), E9 GND (in), E10 GND (in), F4 GND (in), F5 GND (in), F6 GND (in), F7 GND (in), F8 GND (in), F9 GND (in), F10 GND (in), F11 GND (in), F12 SOC_CO_V12D (in), G1 GND (in), G2 GND (in), G6 GND (in), G7 GND (in), G8 GND (in), G9 GND (in), G10 GND (in), G11 GND (in), G12 SOC_CO_V12D (in), H6 GND (in), H7 GND (in), H8 GND (in), H9 GND (in), H10 GND (in), H11 GND (in), H12 BPLL_DVDD_V12D (in), J6 GND (in), J7 GND (in), J8 GND (in), J9 GND (in), J10 GND (in), J11 GND (in), J12 CPLL_DVDD_V12D (in), J13 SOC_IO_V33D (in), K5 SOC_CO_V12D (in), K6 GND (in), K7 GND (in), K8 GND (in), K9 GND (in), K10 GND (in), K11 GND (in), K12 GND (in), K13 SOC_IO_V33D (in), L6 GND (in), L7 GND (in), L8 GND (in), L9 GND (in), L10 GND (in), L11 GND (in), L12 GND (in), L13 BPLL_AVDD_V12A (in), M11 GND (in), M12 GND (in), M13 CPLL_AVDD_V12A (in), N10 SOC_CO_V12D (in), N11 GND (in), N12 GND (in)
part H pins: G1 GND (in), H1 VIN_1P5 (in), H2 VFB_1P2 (in), J1 VOUT_1P2 (in), J2 FB (in), K1 EXT_LDO_1P8 (in), K2 COMP (in), L1 DCDC_V33A (in), L2 OUT_FB_1P8 (in), M1 DCDC_V33D (in), M2 EXT_LDO_1P5 (in), N1 LGATE (in), N2 UGATE (in), P1 DIS_SW (in), P2 GND (in)

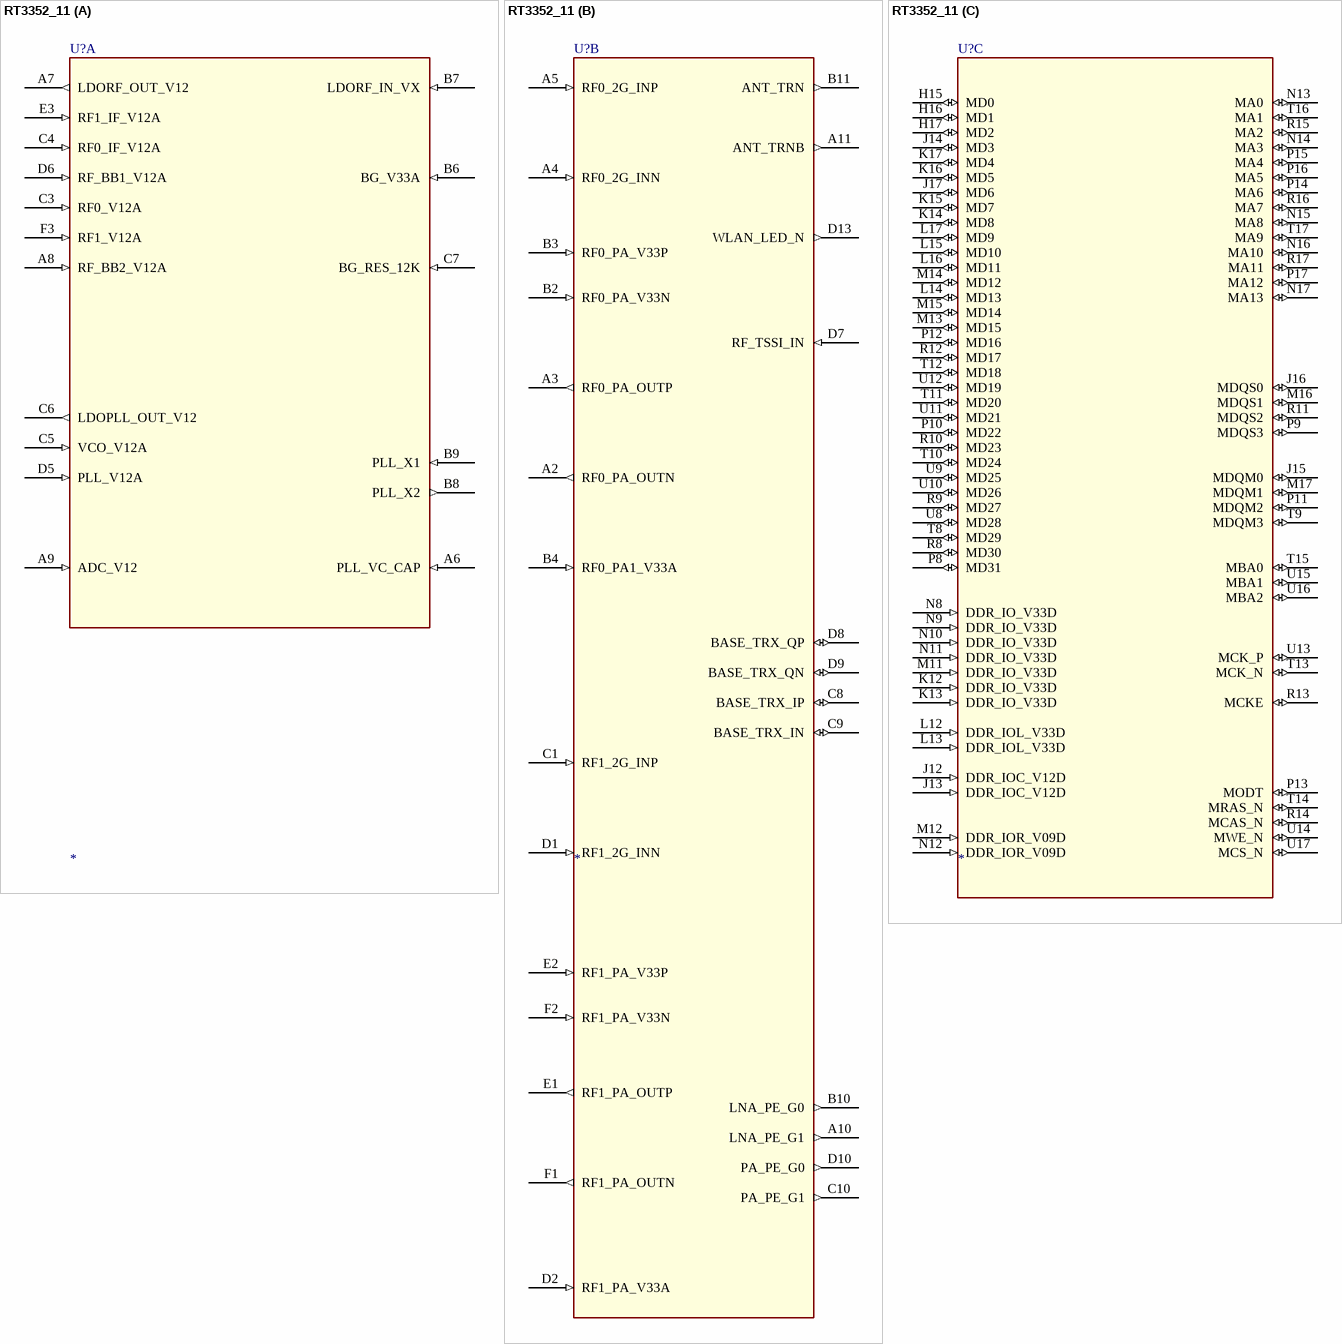
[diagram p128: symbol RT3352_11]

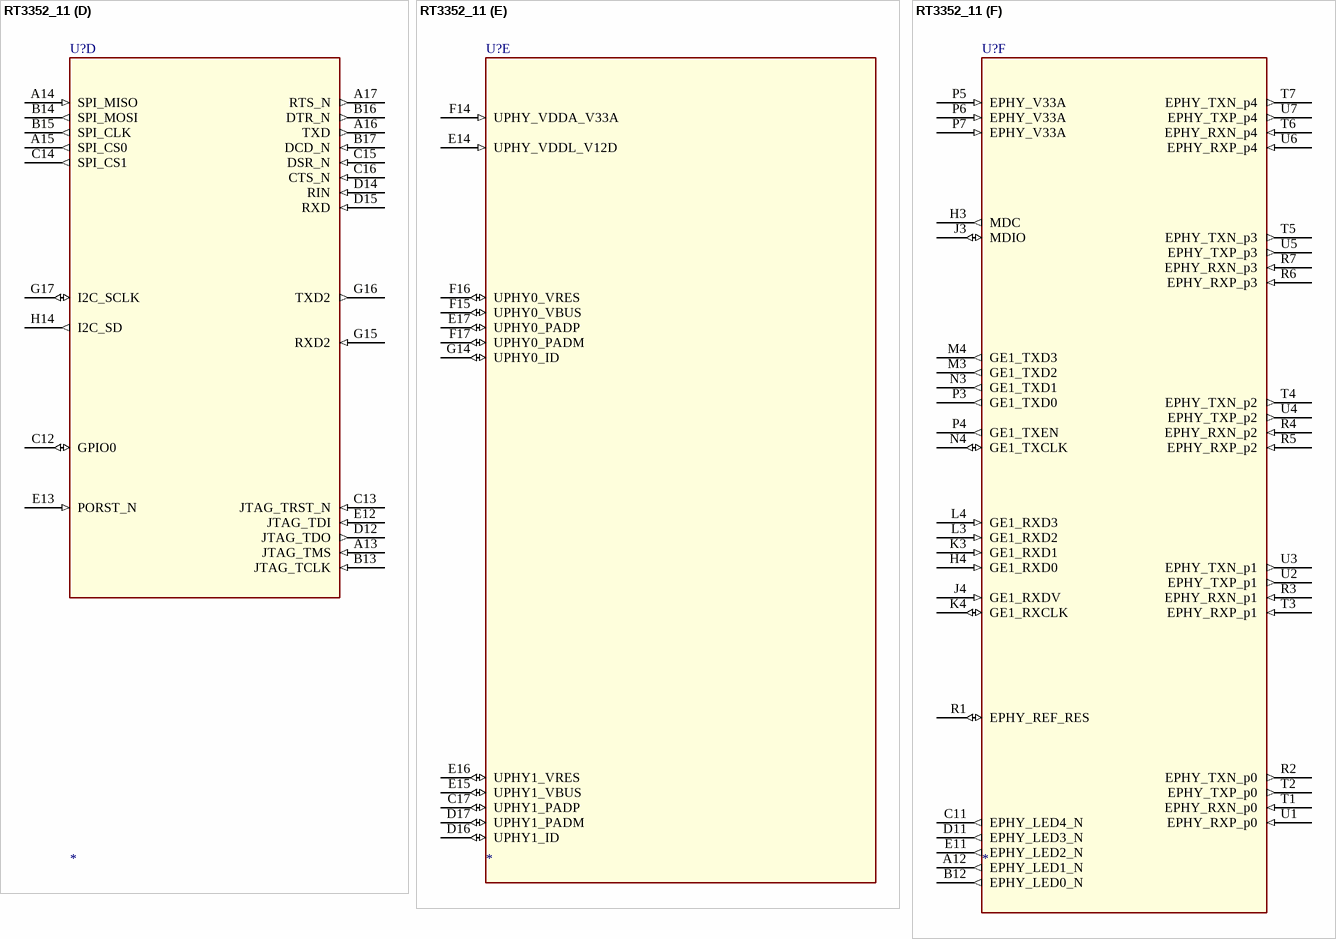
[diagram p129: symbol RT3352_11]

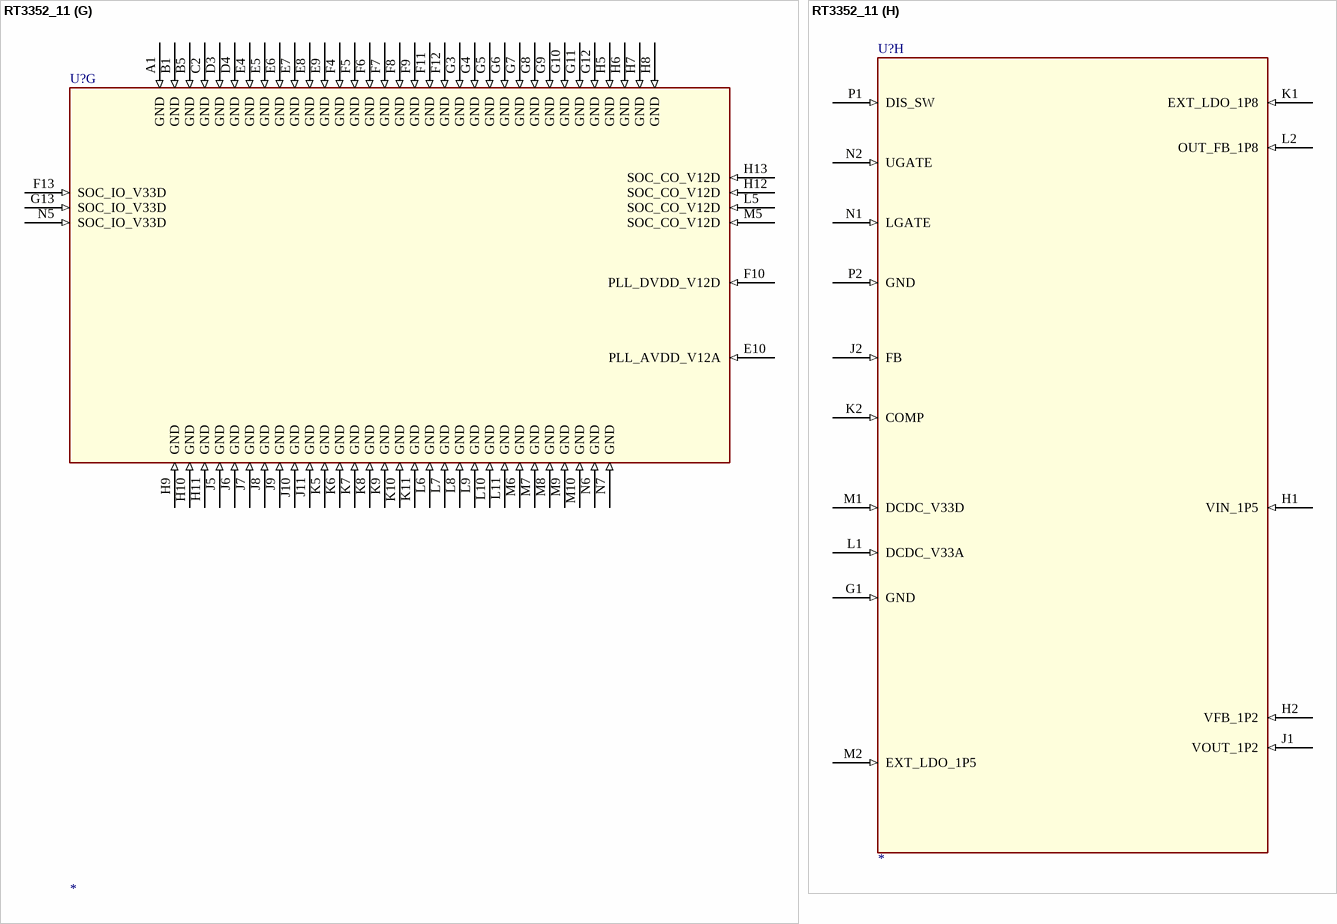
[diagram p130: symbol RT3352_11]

## RT3352_11
designator U?
part A pins: A6 PLL_VC_CAP (in), A7 LDORF_OUT_V12 (out), A8 RF_BB2_V12A (in), A9 ADC_V12 (in), B6 BG_V33A (in), B7 LDORF_IN_VX (in), B8 PLL_X2 (out), B9 PLL_X1 (in), C3 RF0_V12A (in), C4 RF0_IF_V12A (in), C5 VCO_V12A (in), C6 LDOPLL_OUT_V12 (out), C7 BG_RES_12K (in), D5 PLL_V12A (in), D6 RF_BB1_V12A (in), E3 RF1_IF_V12A (in), F3 RF1_V12A (in)
part B pins: A2 RF0_PA_OUTN (out), A3 RF0_PA_OUTP (out), A4 RF0_2G_INN (in), A5 RF0_2G_INP (in), A10 LNA_PE_G1 (out), A11 ANT_TRNB (out), B2 RF0_PA_V33N (in), B3 RF0_PA_V33P (in), B4 RF0_PA1_V33A (in), B10 LNA_PE_G0 (out), B11 ANT_TRN (out), C1 RF1_2G_INP (in), C8 BASE_TRX_IP (io), C9 BASE_TRX_IN (io), C10 PA_PE_G1 (out), D1 RF1_2G_INN (in), D2 RF1_PA_V33A (in), D7 RF_TSSI_IN (in), D8 BASE_TRX_QP (io), D9 BASE_TRX_QN (io), D10 PA_PE_G0 (out), D13 WLAN_LED_N (out), E1 RF1_PA_OUTP (out), E2 RF1_PA_V33P (in), F1 RF1_PA_OUTN (out), F2 RF1_PA_V33N (in)
part C pins: H15 MD0 (io), H16 MD1 (io), H17 MD2 (io), J12 DDR_IOC_V12D (in), J13 DDR_IOC_V12D (in), J14 MD3 (io), J15 MDQM0 (io), J16 MDQS0 (io), J17 MD6 (io), K12 DDR_IO_V33D (in), K13 DDR_IO_V33D (in), K14 MD8 (io), K15 MD7 (io), K16 MD5 (io), K17 MD4 (io), L12 DDR_IOL_V33D (in), L13 DDR_IOL_V33D (in), L14 MD13 (io), L15 MD10 (io), L16 MD11 (io), L17 MD9 (io), M11 DDR_IO_V33D (in), M12 DDR_IOR_V09D (in), M13 MD15 (io), M14 MD12 (io), M15 MD14 (io), M16 MDQS1 (io), M17 MDQM1 (io), N8 DDR_IO_V33D (in), N9 DDR_IO_V33D (in), N10 DDR_IO_V33D (in), N11 DDR_IO_V33D (in), N12 DDR_IOR_V09D (in), N13 MA0 (io), N14 MA3 (io), N15 MA8 (io), N16 MA10 (io), N17 MA13 (io), P8 MD31 (io), P9 MDQS3 (io), P10 MD22 (io), P11 MDQM2 (io), P12 MD16 (io), P13 MODT (io), P14 MA6 (io), P15 MA4 (io), P16 MA5 (io), P17 MA12 (io), R8 MD30 (io), R9 MD27 (io), R10 MD23 (io), R11 MDQS2 (io), R12 MD17 (io), R13 MCKE (io), R14 MCAS_N (io), R15 MA2 (io), R16 MA7 (io), R17 MA11 (io), T8 MD29 (io), T9 MDQM3 (io), T10 MD24 (io), T11 MD20 (io), T12 MD18 (io), T13 MCK_N (io), T14 MRAS_N (io), T15 MBA0 (io), T16 MA1 (io), T17 MA9 (io), U8 MD28 (io), U9 MD25 (io), U10 MD26 (io), U11 MD21 (io), U12 MD19 (io), U13 MCK_P (io), U14 MWE_N (io), U15 MBA1 (io), U16 MBA2 (io), U17 MCS_N (io)
part D pins: A13 JTAG_TMS (in), A14 SPI_MISO (in), A15 SPI_CS0 (out), A16 TXD (out), A17 RTS_N (out), B13 JTAG_TCLK (in), B14 SPI_MOSI (out), B15 SPI_CLK (out), B16 DTR_N (out), B17 DCD_N (in), C12 GPIO0 (io), C13 JTAG_TRST_N (in), C14 SPI_CS1 (out), C15 DSR_N (in), C16 CTS_N (in), D12 JTAG_TDO (out), D14 RIN (in), D15 RXD (in), E12 JTAG_TDI (in), E13 PORST_N (in), G15 RXD2 (in), G16 TXD2 (out), G17 I2C_SCLK (io), H14 I2C_SD (out)
part E pins: C17 UPHY1_PADP (io), D16 UPHY1_ID (io), D17 UPHY1_PADM (io), E14 UPHY_VDDL_V12D (in), E15 UPHY1_VBUS (io), E16 UPHY1_VRES (io), E17 UPHY0_PADP (io), F14 UPHY_VDDA_V33A (in), F15 UPHY0_VBUS (io), F16 UPHY0_VRES (io), F17 UPHY0_PADM (io), G14 UPHY0_ID (io)
part F pins: A12 EPHY_LED1_N (out), B12 EPHY_LED0_N (out), C11 EPHY_LED4_N (out), D11 EPHY_LED3_N (out), E11 EPHY_LED2_N (out), H3 MDC (out), H4 GE1_RXD0 (in), J3 MDIO (io), J4 GE1_RXDV (in), K3 GE1_RXD1 (in), K4 GE1_RXCLK (io), L3 GE1_RXD2 (in), L4 GE1_RXD3 (in), M3 GE1_TXD2 (out), M4 GE1_TXD3 (out), N3 GE1_TXD1 (out), N4 GE1_TXCLK (io), P3 GE1_TXD0 (out), P4 GE1_TXEN (out), P5 EPHY_V33A (in), P6 EPHY_V33A (in), P7 EPHY_V33A (in), R1 EPHY_REF_RES (io), R2 EPHY_TXN_p0 (out), R3 EPHY_RXN_p1 (in), R4 EPHY_RXN_p2 (in), R5 EPHY_RXP_p2 (in), R6 EPHY_RXP_p3 (in), R7 EPHY_RXN_p3 (in), T1 EPHY_RXN_p0 (in), T2 EPHY_TXP_p0 (out), T3 EPHY_RXP_p1 (in), T4 EPHY_TXN_p2 (out), T5 EPHY_TXN_p3 (out), T6 EPHY_RXN_p4 (in), T7 EPHY_TXN_p4 (out), U1 EPHY_RXP_p0 (in), U2 EPHY_TXP_p1 (out), U3 EPHY_TXN_p1 (out), U4 EPHY_TXP_p2 (out), U5 EPHY_TXP_p3 (out), U6 EPHY_RXP_p4 (in), U7 EPHY_TXP_p4 (out)
part G pins: A1 GND (in), B1 GND (in), B5 GND (in), C2 GND (in), D3 GND (in), D4 GND (in), E4 GND (in), E5 GND (in), E6 GND (in), E7 GND (in), E8 GND (in), E9 GND (in), E10 PLL_AVDD_V12A (in), F4 GND (in), F5 GND (in), F6 GND (in), F7 GND (in), F8 GND (in), F9 GND (in), F10 PLL_DVDD_V12D (in), F11 GND (in), F12 GND (in), F13 SOC_IO_V33D (in), G3 GND (in), G4 GND (in), G5 GND (in), G6 GND (in), G7 GND (in), G8 GND (in), G9 GND (in), G10 GND (in), G11 GND (in), G12 GND (in), G13 SOC_IO_V33D (in), H5 GND (in), H6 GND (in), H7 GND (in), H8 GND (in), H9 GND (in), H10 GND (in), H11 GND (in), H12 SOC_CO_V12D (in), H13 SOC_CO_V12D (in), J5 GND (in), J6 GND (in), J7 GND (in), J8 GND (in), J9 GND (in), J10 GND (in), J11 GND (in), K5 GND (in), K6 GND (in), K7 GND (in), K8 GND (in), K9 GND (in), K10 GND (in), K11 GND (in), L5 SOC_CO_V12D (in), L6 GND (in), L7 GND (in), L8 GND (in), L9 GND (in), L10 GND (in), L11 GND (in), M5 SOC_CO_V12D (in), M6 GND (in), M7 GND (in), M8 GND (in), M9 GND (in), M10 GND (in), N5 SOC_IO_V33D (in), N6 GND (in), N7 GND (in)
part H pins: G1 GND (in), H1 VIN_1P5 (in), H2 VFB_1P2 (in), J1 VOUT_1P2 (in), J2 FB (in), K1 EXT_LDO_1P8 (in), K2 COMP (in), L1 DCDC_V33A (in), L2 OUT_FB_1P8 (in), M1 DCDC_V33D (in), M2 EXT_LDO_1P5 (in), N1 LGATE (in), N2 UGATE (in), P1 DIS_SW (in), P2 GND (in)

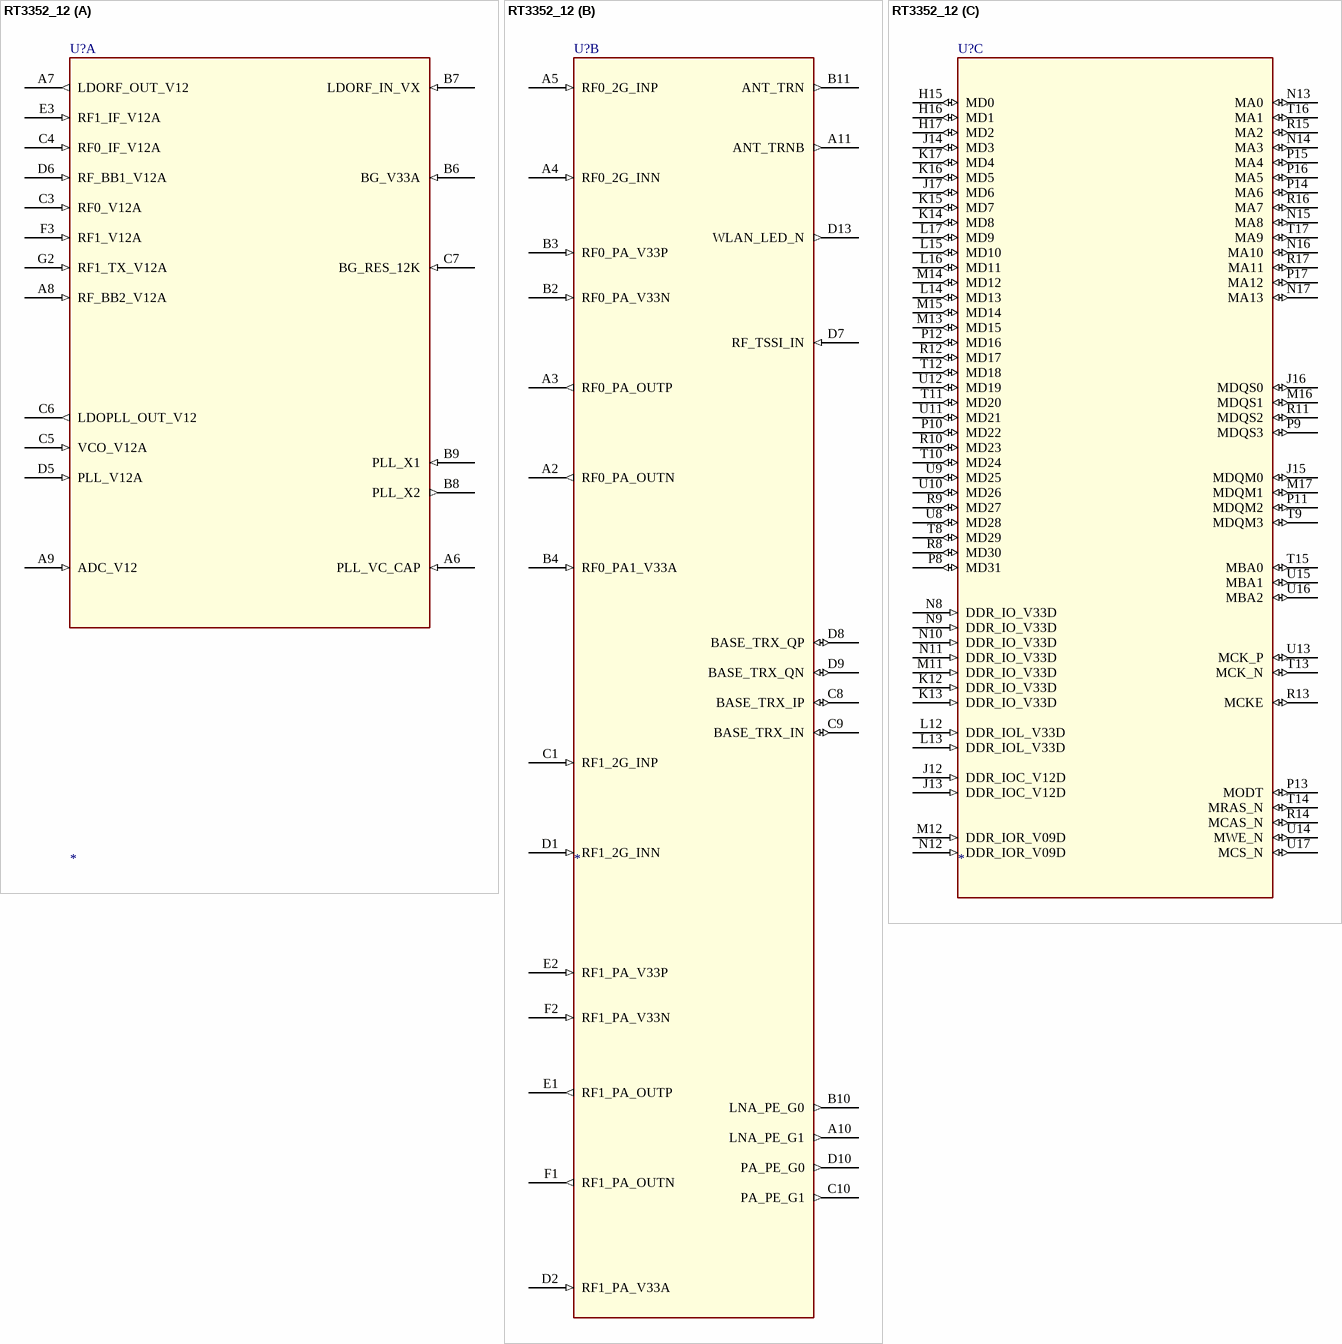
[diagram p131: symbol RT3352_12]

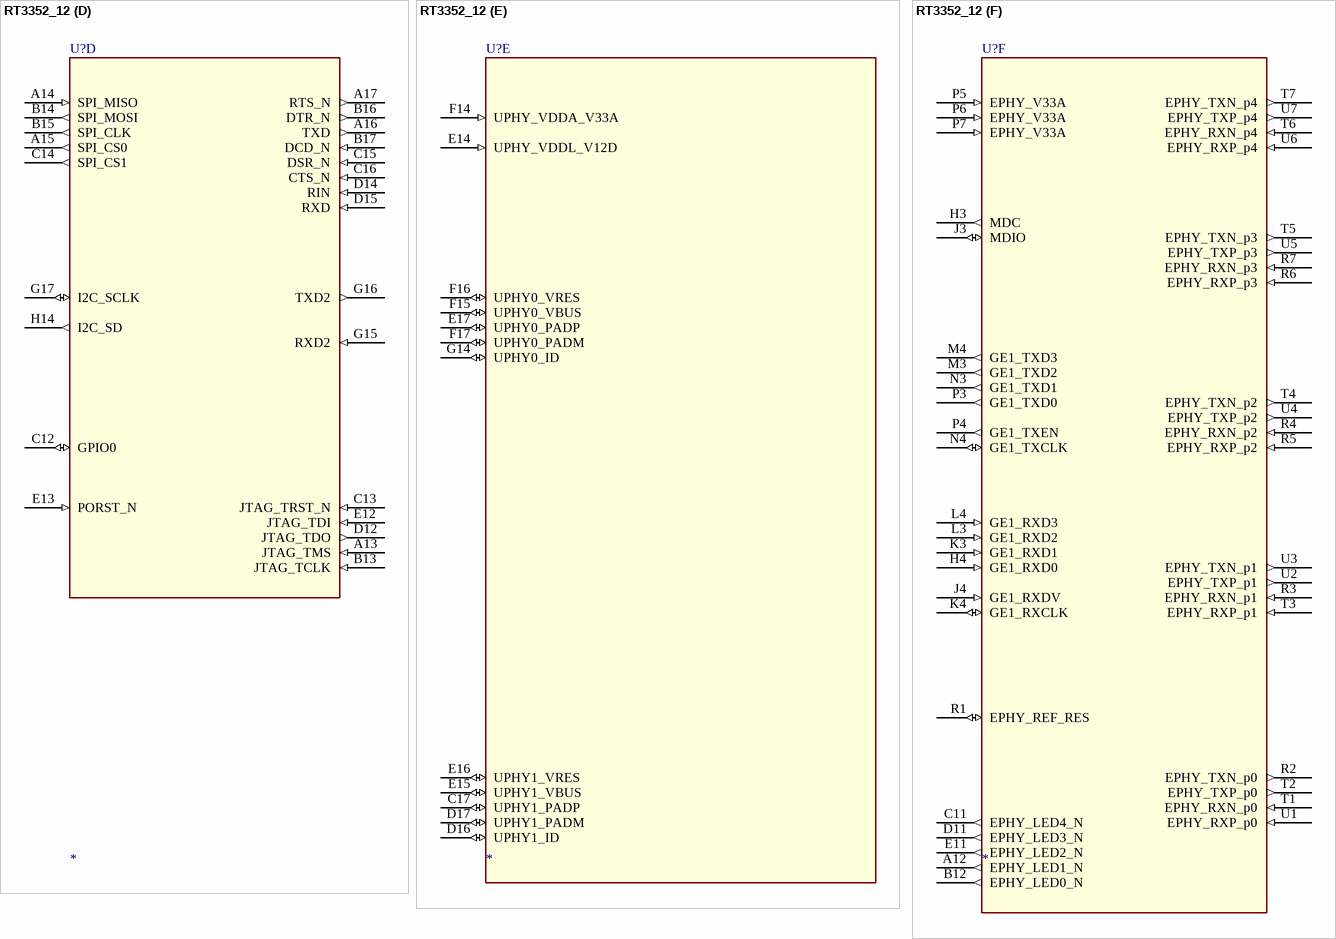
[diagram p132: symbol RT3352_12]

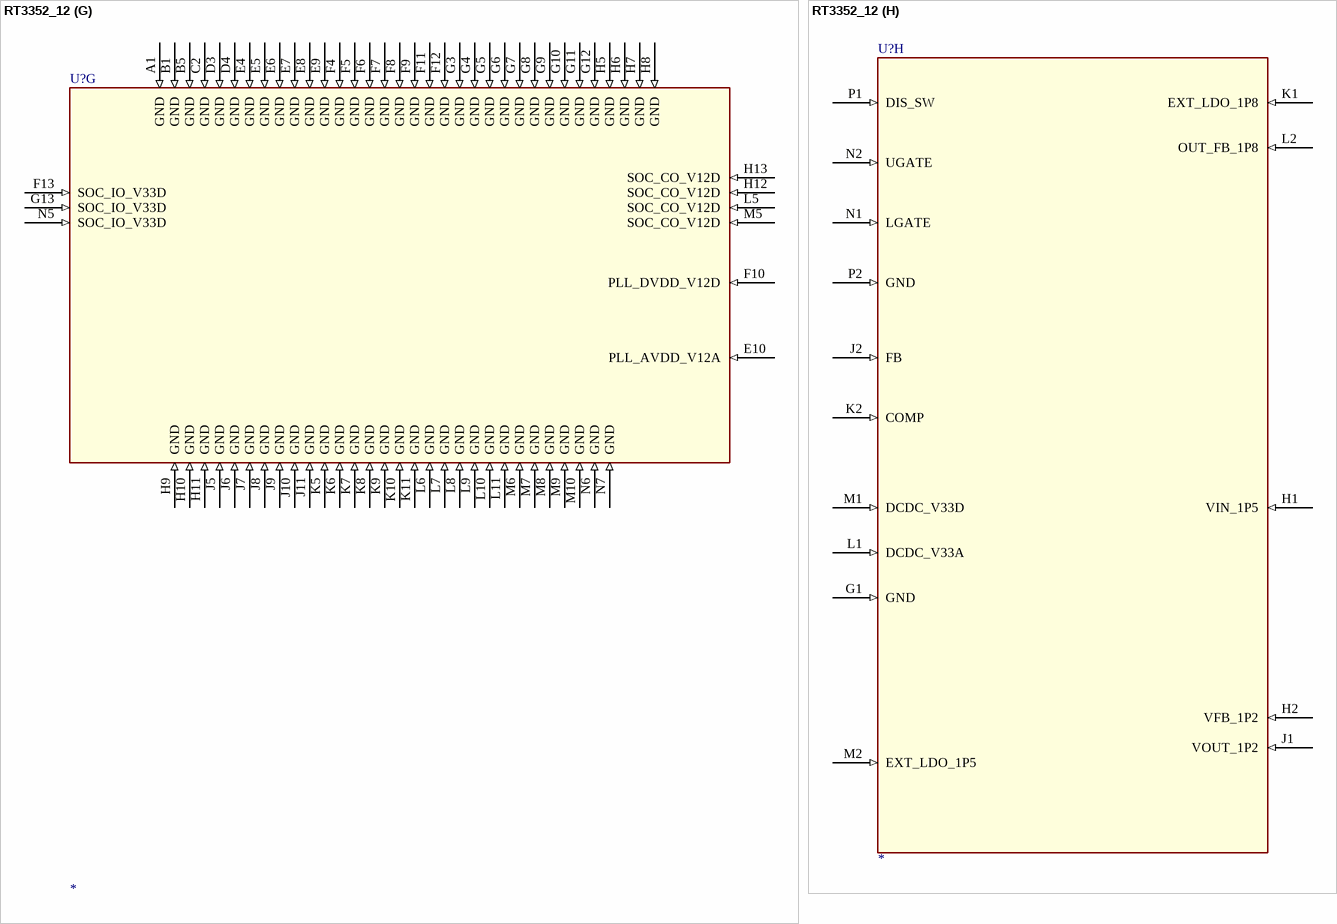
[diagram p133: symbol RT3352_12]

## RT3352_12
designator U?
part A pins: A6 PLL_VC_CAP (in), A7 LDORF_OUT_V12 (out), A8 RF_BB2_V12A (in), A9 ADC_V12 (in), B6 BG_V33A (in), B7 LDORF_IN_VX (in), B8 PLL_X2 (out), B9 PLL_X1 (in), C3 RF0_V12A (in), C4 RF0_IF_V12A (in), C5 VCO_V12A (in), C6 LDOPLL_OUT_V12 (out), C7 BG_RES_12K (in), D5 PLL_V12A (in), D6 RF_BB1_V12A (in), E3 RF1_IF_V12A (in), F3 RF1_V12A (in), G2 RF1_TX_V12A (in)
part B pins: A2 RF0_PA_OUTN (out), A3 RF0_PA_OUTP (out), A4 RF0_2G_INN (in), A5 RF0_2G_INP (in), A10 LNA_PE_G1 (out), A11 ANT_TRNB (out), B2 RF0_PA_V33N (in), B3 RF0_PA_V33P (in), B4 RF0_PA1_V33A (in), B10 LNA_PE_G0 (out), B11 ANT_TRN (out), C1 RF1_2G_INP (in), C8 BASE_TRX_IP (io), C9 BASE_TRX_IN (io), C10 PA_PE_G1 (out), D1 RF1_2G_INN (in), D2 RF1_PA_V33A (in), D7 RF_TSSI_IN (in), D8 BASE_TRX_QP (io), D9 BASE_TRX_QN (io), D10 PA_PE_G0 (out), D13 WLAN_LED_N (out), E1 RF1_PA_OUTP (out), E2 RF1_PA_V33P (in), F1 RF1_PA_OUTN (out), F2 RF1_PA_V33N (in)
part C pins: H15 MD0 (io), H16 MD1 (io), H17 MD2 (io), J12 DDR_IOC_V12D (in), J13 DDR_IOC_V12D (in), J14 MD3 (io), J15 MDQM0 (io), J16 MDQS0 (io), J17 MD6 (io), K12 DDR_IO_V33D (in), K13 DDR_IO_V33D (in), K14 MD8 (io), K15 MD7 (io), K16 MD5 (io), K17 MD4 (io), L12 DDR_IOL_V33D (in), L13 DDR_IOL_V33D (in), L14 MD13 (io), L15 MD10 (io), L16 MD11 (io), L17 MD9 (io), M11 DDR_IO_V33D (in), M12 DDR_IOR_V09D (in), M13 MD15 (io), M14 MD12 (io), M15 MD14 (io), M16 MDQS1 (io), M17 MDQM1 (io), N8 DDR_IO_V33D (in), N9 DDR_IO_V33D (in), N10 DDR_IO_V33D (in), N11 DDR_IO_V33D (in), N12 DDR_IOR_V09D (in), N13 MA0 (io), N14 MA3 (io), N15 MA8 (io), N16 MA10 (io), N17 MA13 (io), P8 MD31 (io), P9 MDQS3 (io), P10 MD22 (io), P11 MDQM2 (io), P12 MD16 (io), P13 MODT (io), P14 MA6 (io), P15 MA4 (io), P16 MA5 (io), P17 MA12 (io), R8 MD30 (io), R9 MD27 (io), R10 MD23 (io), R11 MDQS2 (io), R12 MD17 (io), R13 MCKE (io), R14 MCAS_N (io), R15 MA2 (io), R16 MA7 (io), R17 MA11 (io), T8 MD29 (io), T9 MDQM3 (io), T10 MD24 (io), T11 MD20 (io), T12 MD18 (io), T13 MCK_N (io), T14 MRAS_N (io), T15 MBA0 (io), T16 MA1 (io), T17 MA9 (io), U8 MD28 (io), U9 MD25 (io), U10 MD26 (io), U11 MD21 (io), U12 MD19 (io), U13 MCK_P (io), U14 MWE_N (io), U15 MBA1 (io), U16 MBA2 (io), U17 MCS_N (io)
part D pins: A13 JTAG_TMS (in), A14 SPI_MISO (in), A15 SPI_CS0 (out), A16 TXD (out), A17 RTS_N (out), B13 JTAG_TCLK (in), B14 SPI_MOSI (out), B15 SPI_CLK (out), B16 DTR_N (out), B17 DCD_N (in), C12 GPIO0 (io), C13 JTAG_TRST_N (in), C14 SPI_CS1 (out), C15 DSR_N (in), C16 CTS_N (in), D12 JTAG_TDO (out), D14 RIN (in), D15 RXD (in), E12 JTAG_TDI (in), E13 PORST_N (in), G15 RXD2 (in), G16 TXD2 (out), G17 I2C_SCLK (io), H14 I2C_SD (out)
part E pins: C17 UPHY1_PADP (io), D16 UPHY1_ID (io), D17 UPHY1_PADM (io), E14 UPHY_VDDL_V12D (in), E15 UPHY1_VBUS (io), E16 UPHY1_VRES (io), E17 UPHY0_PADP (io), F14 UPHY_VDDA_V33A (in), F15 UPHY0_VBUS (io), F16 UPHY0_VRES (io), F17 UPHY0_PADM (io), G14 UPHY0_ID (io)
part F pins: A12 EPHY_LED1_N (out), B12 EPHY_LED0_N (out), C11 EPHY_LED4_N (out), D11 EPHY_LED3_N (out), E11 EPHY_LED2_N (out), H3 MDC (out), H4 GE1_RXD0 (in), J3 MDIO (io), J4 GE1_RXDV (in), K3 GE1_RXD1 (in), K4 GE1_RXCLK (io), L3 GE1_RXD2 (in), L4 GE1_RXD3 (in), M3 GE1_TXD2 (out), M4 GE1_TXD3 (out), N3 GE1_TXD1 (out), N4 GE1_TXCLK (io), P3 GE1_TXD0 (out), P4 GE1_TXEN (out), P5 EPHY_V33A (in), P6 EPHY_V33A (in), P7 EPHY_V33A (in), R1 EPHY_REF_RES (io), R2 EPHY_TXN_p0 (out), R3 EPHY_RXN_p1 (in), R4 EPHY_RXN_p2 (in), R5 EPHY_RXP_p2 (in), R6 EPHY_RXP_p3 (in), R7 EPHY_RXN_p3 (in), T1 EPHY_RXN_p0 (in), T2 EPHY_TXP_p0 (out), T3 EPHY_RXP_p1 (in), T4 EPHY_TXN_p2 (out), T5 EPHY_TXN_p3 (out), T6 EPHY_RXN_p4 (in), T7 EPHY_TXN_p4 (out), U1 EPHY_RXP_p0 (in), U2 EPHY_TXP_p1 (out), U3 EPHY_TXN_p1 (out), U4 EPHY_TXP_p2 (out), U5 EPHY_TXP_p3 (out), U6 EPHY_RXP_p4 (in), U7 EPHY_TXP_p4 (out)
part G pins: A1 GND (in), B1 GND (in), B5 GND (in), C2 GND (in), D3 GND (in), D4 GND (in), E4 GND (in), E5 GND (in), E6 GND (in), E7 GND (in), E8 GND (in), E9 GND (in), E10 PLL_AVDD_V12A (in), F4 GND (in), F5 GND (in), F6 GND (in), F7 GND (in), F8 GND (in), F9 GND (in), F10 PLL_DVDD_V12D (in), F11 GND (in), F12 GND (in), F13 SOC_IO_V33D (in), G3 GND (in), G4 GND (in), G5 GND (in), G6 GND (in), G7 GND (in), G8 GND (in), G9 GND (in), G10 GND (in), G11 GND (in), G12 GND (in), G13 SOC_IO_V33D (in), H5 GND (in), H6 GND (in), H7 GND (in), H8 GND (in), H9 GND (in), H10 GND (in), H11 GND (in), H12 SOC_CO_V12D (in), H13 SOC_CO_V12D (in), J5 GND (in), J6 GND (in), J7 GND (in), J8 GND (in), J9 GND (in), J10 GND (in), J11 GND (in), K5 GND (in), K6 GND (in), K7 GND (in), K8 GND (in), K9 GND (in), K10 GND (in), K11 GND (in), L5 SOC_CO_V12D (in), L6 GND (in), L7 GND (in), L8 GND (in), L9 GND (in), L10 GND (in), L11 GND (in), M5 SOC_CO_V12D (in), M6 GND (in), M7 GND (in), M8 GND (in), M9 GND (in), M10 GND (in), N5 SOC_IO_V33D (in), N6 GND (in), N7 GND (in)
part H pins: G1 GND (in), H1 VIN_1P5 (in), H2 VFB_1P2 (in), J1 VOUT_1P2 (in), J2 FB (in), K1 EXT_LDO_1P8 (in), K2 COMP (in), L1 DCDC_V33A (in), L2 OUT_FB_1P8 (in), M1 DCDC_V33D (in), M2 EXT_LDO_1P5 (in), N1 LGATE (in), N2 UGATE (in), P1 DIS_SW (in), P2 GND (in)

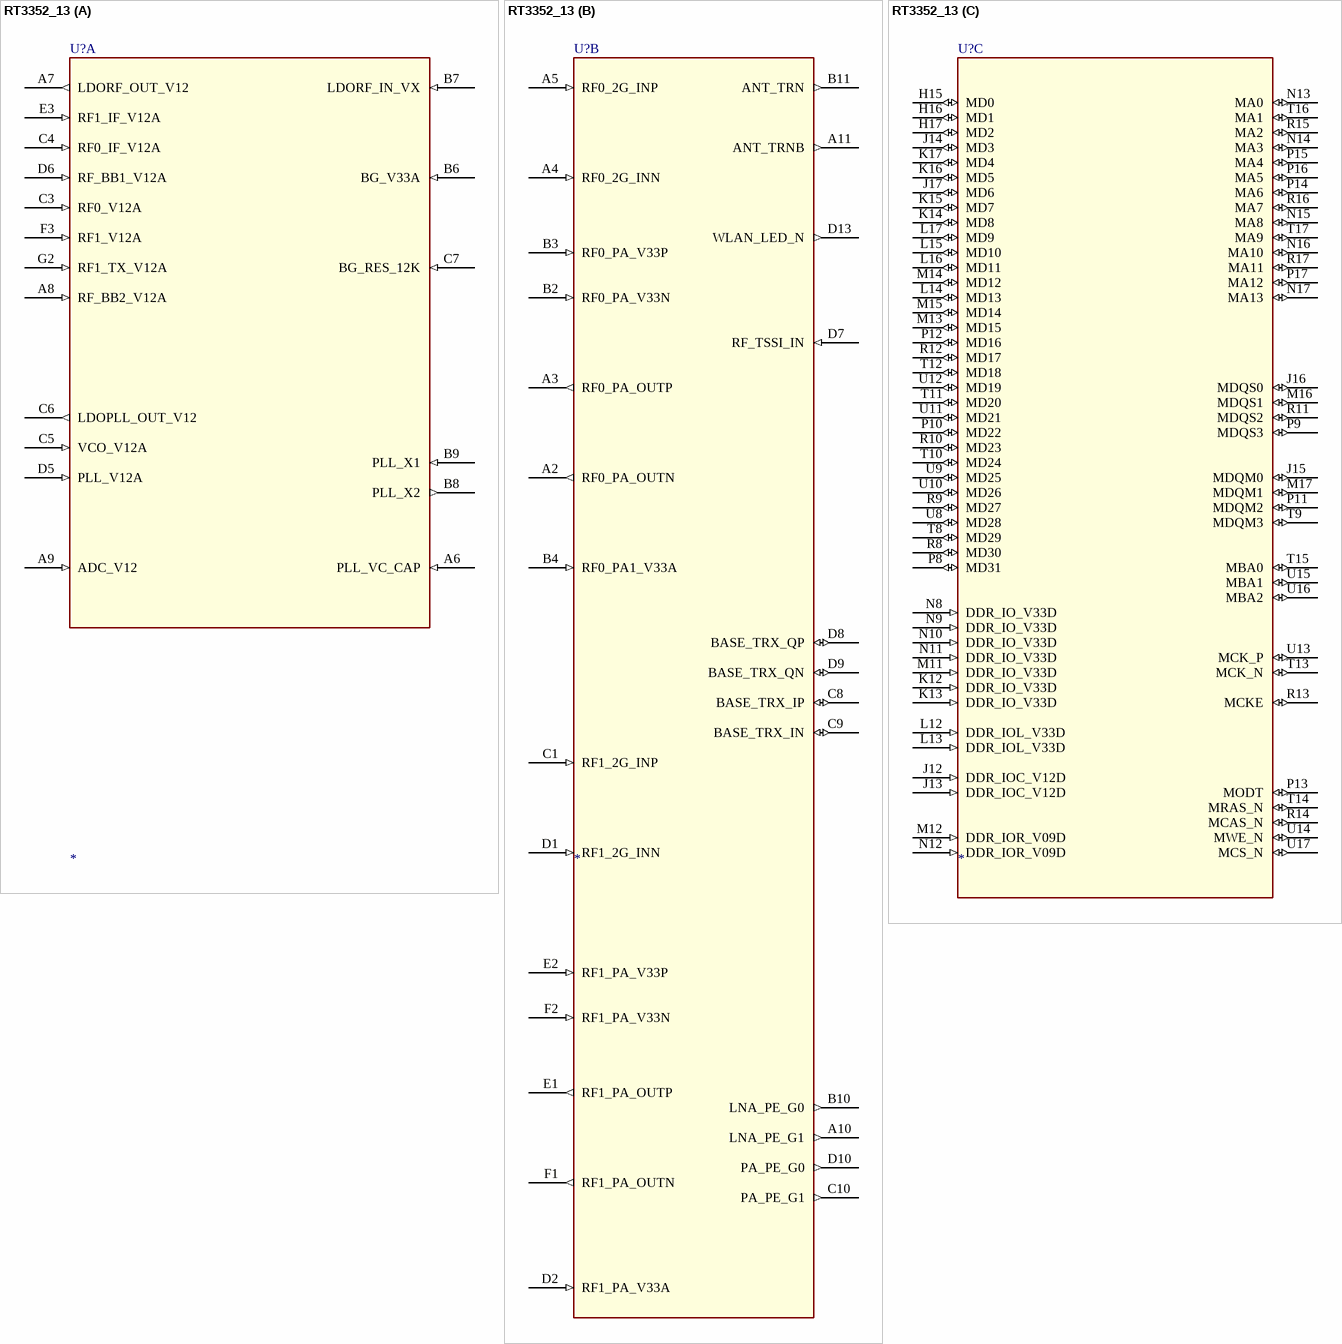
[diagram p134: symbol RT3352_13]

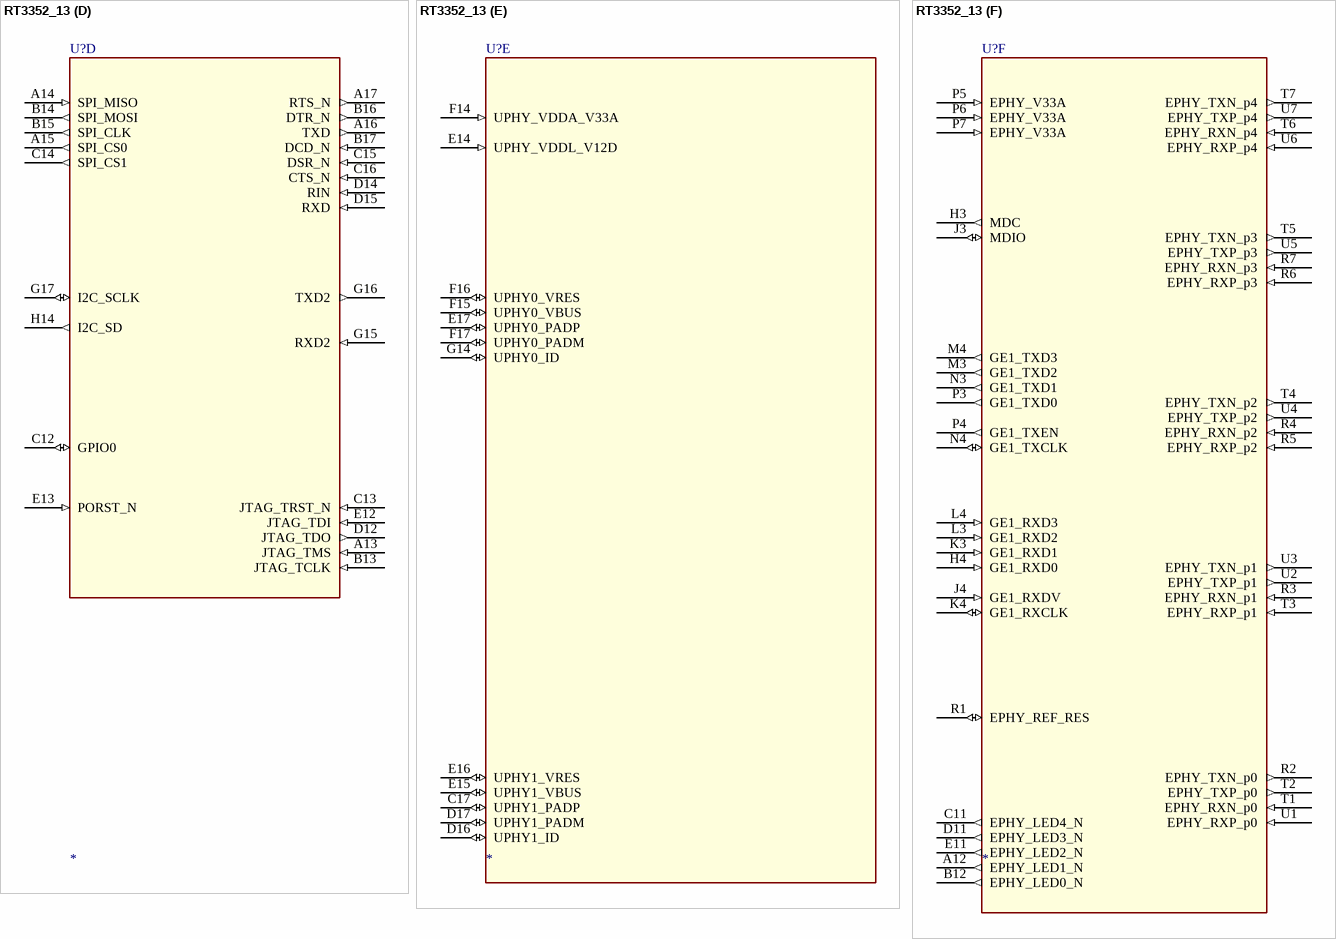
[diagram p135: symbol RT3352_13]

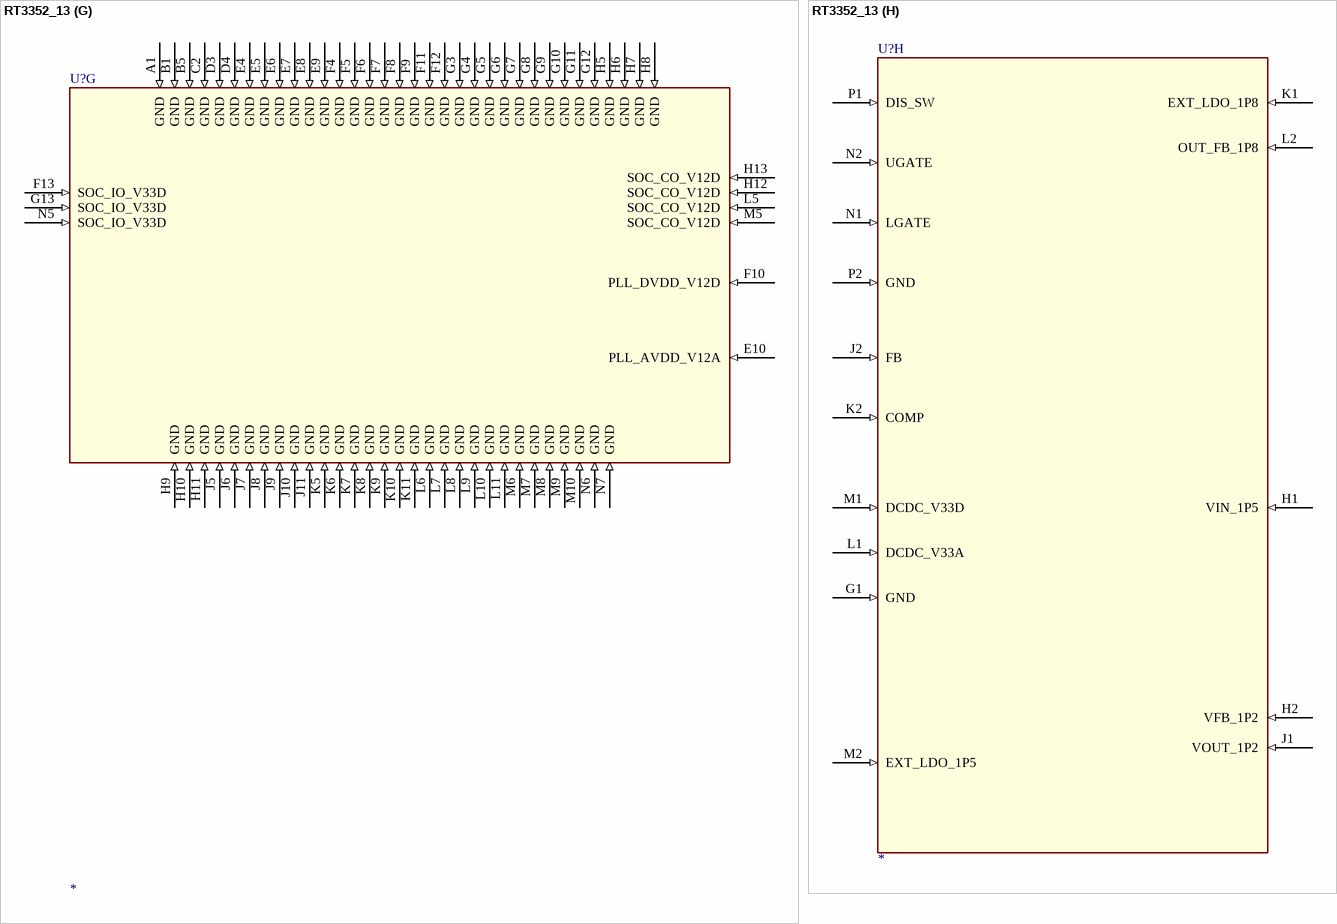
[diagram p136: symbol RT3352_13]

## RT3352_13
designator U?
part A pins: A6 PLL_VC_CAP (in), A7 LDORF_OUT_V12 (out), A8 RF_BB2_V12A (in), A9 ADC_V12 (in), B6 BG_V33A (in), B7 LDORF_IN_VX (in), B8 PLL_X2 (out), B9 PLL_X1 (in), C3 RF0_V12A (in), C4 RF0_IF_V12A (in), C5 VCO_V12A (in), C6 LDOPLL_OUT_V12 (out), C7 BG_RES_12K (in), D5 PLL_V12A (in), D6 RF_BB1_V12A (in), E3 RF1_IF_V12A (in), F3 RF1_V12A (in), G2 RF1_TX_V12A (in)
part B pins: A2 RF0_PA_OUTN (out), A3 RF0_PA_OUTP (out), A4 RF0_2G_INN (in), A5 RF0_2G_INP (in), A10 LNA_PE_G1 (out), A11 ANT_TRNB (out), B2 RF0_PA_V33N (in), B3 RF0_PA_V33P (in), B4 RF0_PA1_V33A (in), B10 LNA_PE_G0 (out), B11 ANT_TRN (out), C1 RF1_2G_INP (in), C8 BASE_TRX_IP (io), C9 BASE_TRX_IN (io), C10 PA_PE_G1 (out), D1 RF1_2G_INN (in), D2 RF1_PA_V33A (in), D7 RF_TSSI_IN (in), D8 BASE_TRX_QP (io), D9 BASE_TRX_QN (io), D10 PA_PE_G0 (out), D13 WLAN_LED_N (out), E1 RF1_PA_OUTP (out), E2 RF1_PA_V33P (in), F1 RF1_PA_OUTN (out), F2 RF1_PA_V33N (in)
part C pins: H15 MD0 (io), H16 MD1 (io), H17 MD2 (io), J12 DDR_IOC_V12D (in), J13 DDR_IOC_V12D (in), J14 MD3 (io), J15 MDQM0 (io), J16 MDQS0 (io), J17 MD6 (io), K12 DDR_IO_V33D (in), K13 DDR_IO_V33D (in), K14 MD8 (io), K15 MD7 (io), K16 MD5 (io), K17 MD4 (io), L12 DDR_IOL_V33D (in), L13 DDR_IOL_V33D (in), L14 MD13 (io), L15 MD10 (io), L16 MD11 (io), L17 MD9 (io), M11 DDR_IO_V33D (in), M12 DDR_IOR_V09D (in), M13 MD15 (io), M14 MD12 (io), M15 MD14 (io), M16 MDQS1 (io), M17 MDQM1 (io), N8 DDR_IO_V33D (in), N9 DDR_IO_V33D (in), N10 DDR_IO_V33D (in), N11 DDR_IO_V33D (in), N12 DDR_IOR_V09D (in), N13 MA0 (io), N14 MA3 (io), N15 MA8 (io), N16 MA10 (io), N17 MA13 (io), P8 MD31 (io), P9 MDQS3 (io), P10 MD22 (io), P11 MDQM2 (io), P12 MD16 (io), P13 MODT (io), P14 MA6 (io), P15 MA4 (io), P16 MA5 (io), P17 MA12 (io), R8 MD30 (io), R9 MD27 (io), R10 MD23 (io), R11 MDQS2 (io), R12 MD17 (io), R13 MCKE (io), R14 MCAS_N (io), R15 MA2 (io), R16 MA7 (io), R17 MA11 (io), T8 MD29 (io), T9 MDQM3 (io), T10 MD24 (io), T11 MD20 (io), T12 MD18 (io), T13 MCK_N (io), T14 MRAS_N (io), T15 MBA0 (io), T16 MA1 (io), T17 MA9 (io), U8 MD28 (io), U9 MD25 (io), U10 MD26 (io), U11 MD21 (io), U12 MD19 (io), U13 MCK_P (io), U14 MWE_N (io), U15 MBA1 (io), U16 MBA2 (io), U17 MCS_N (io)
part D pins: A13 JTAG_TMS (in), A14 SPI_MISO (in), A15 SPI_CS0 (out), A16 TXD (out), A17 RTS_N (out), B13 JTAG_TCLK (in), B14 SPI_MOSI (out), B15 SPI_CLK (out), B16 DTR_N (out), B17 DCD_N (in), C12 GPIO0 (io), C13 JTAG_TRST_N (in), C14 SPI_CS1 (out), C15 DSR_N (in), C16 CTS_N (in), D12 JTAG_TDO (out), D14 RIN (in), D15 RXD (in), E12 JTAG_TDI (in), E13 PORST_N (in), G15 RXD2 (in), G16 TXD2 (out), G17 I2C_SCLK (io), H14 I2C_SD (out)
part E pins: C17 UPHY1_PADP (io), D16 UPHY1_ID (io), D17 UPHY1_PADM (io), E14 UPHY_VDDL_V12D (in), E15 UPHY1_VBUS (io), E16 UPHY1_VRES (io), E17 UPHY0_PADP (io), F14 UPHY_VDDA_V33A (in), F15 UPHY0_VBUS (io), F16 UPHY0_VRES (io), F17 UPHY0_PADM (io), G14 UPHY0_ID (io)
part F pins: A12 EPHY_LED1_N (out), B12 EPHY_LED0_N (out), C11 EPHY_LED4_N (out), D11 EPHY_LED3_N (out), E11 EPHY_LED2_N (out), H3 MDC (out), H4 GE1_RXD0 (in), J3 MDIO (io), J4 GE1_RXDV (in), K3 GE1_RXD1 (in), K4 GE1_RXCLK (io), L3 GE1_RXD2 (in), L4 GE1_RXD3 (in), M3 GE1_TXD2 (out), M4 GE1_TXD3 (out), N3 GE1_TXD1 (out), N4 GE1_TXCLK (io), P3 GE1_TXD0 (out), P4 GE1_TXEN (out), P5 EPHY_V33A (in), P6 EPHY_V33A (in), P7 EPHY_V33A (in), R1 EPHY_REF_RES (io), R2 EPHY_TXN_p0 (out), R3 EPHY_RXN_p1 (in), R4 EPHY_RXN_p2 (in), R5 EPHY_RXP_p2 (in), R6 EPHY_RXP_p3 (in), R7 EPHY_RXN_p3 (in), T1 EPHY_RXN_p0 (in), T2 EPHY_TXP_p0 (out), T3 EPHY_RXP_p1 (in), T4 EPHY_TXN_p2 (out), T5 EPHY_TXN_p3 (out), T6 EPHY_RXN_p4 (in), T7 EPHY_TXN_p4 (out), U1 EPHY_RXP_p0 (in), U2 EPHY_TXP_p1 (out), U3 EPHY_TXN_p1 (out), U4 EPHY_TXP_p2 (out), U5 EPHY_TXP_p3 (out), U6 EPHY_RXP_p4 (in), U7 EPHY_TXP_p4 (out)
part G pins: A1 GND (in), B1 GND (in), B5 GND (in), C2 GND (in), D3 GND (in), D4 GND (in), E4 GND (in), E5 GND (in), E6 GND (in), E7 GND (in), E8 GND (in), E9 GND (in), E10 PLL_AVDD_V12A (in), F4 GND (in), F5 GND (in), F6 GND (in), F7 GND (in), F8 GND (in), F9 GND (in), F10 PLL_DVDD_V12D (in), F11 GND (in), F12 GND (in), F13 SOC_IO_V33D (in), G3 GND (in), G4 GND (in), G5 GND (in), G6 GND (in), G7 GND (in), G8 GND (in), G9 GND (in), G10 GND (in), G11 GND (in), G12 GND (in), G13 SOC_IO_V33D (in), H5 GND (in), H6 GND (in), H7 GND (in), H8 GND (in), H9 GND (in), H10 GND (in), H11 GND (in), H12 SOC_CO_V12D (in), H13 SOC_CO_V12D (in), J5 GND (in), J6 GND (in), J7 GND (in), J8 GND (in), J9 GND (in), J10 GND (in), J11 GND (in), K5 GND (in), K6 GND (in), K7 GND (in), K8 GND (in), K9 GND (in), K10 GND (in), K11 GND (in), L5 SOC_CO_V12D (in), L6 GND (in), L7 GND (in), L8 GND (in), L9 GND (in), L10 GND (in), L11 GND (in), M5 SOC_CO_V12D (in), M6 GND (in), M7 GND (in), M8 GND (in), M9 GND (in), M10 GND (in), N5 SOC_IO_V33D (in), N6 GND (in), N7 GND (in)
part H pins: G1 GND (in), H1 VIN_1P5 (in), H2 VFB_1P2 (in), J1 VOUT_1P2 (in), J2 FB (in), K1 EXT_LDO_1P8 (in), K2 COMP (in), L1 DCDC_V33A (in), L2 OUT_FB_1P8 (in), M1 DCDC_V33D (in), M2 EXT_LDO_1P5 (in), N1 LGATE (in), N2 UGATE (in), P1 DIS_SW (in), P2 GND (in)

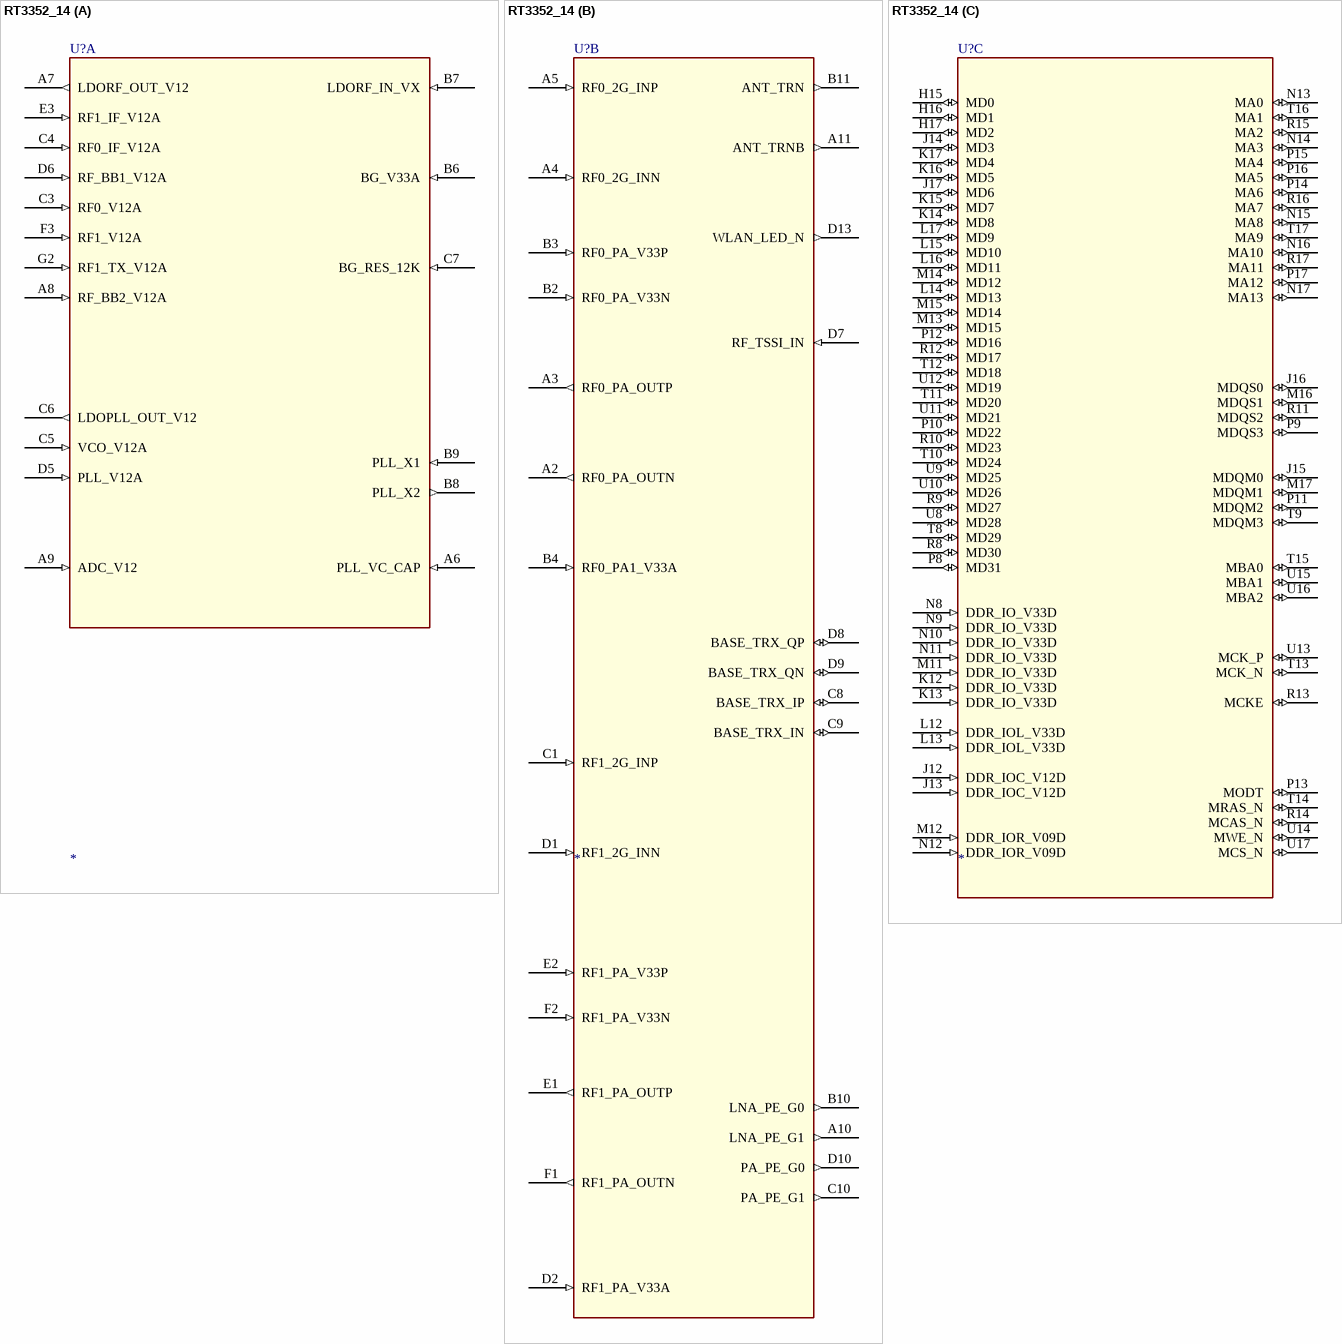
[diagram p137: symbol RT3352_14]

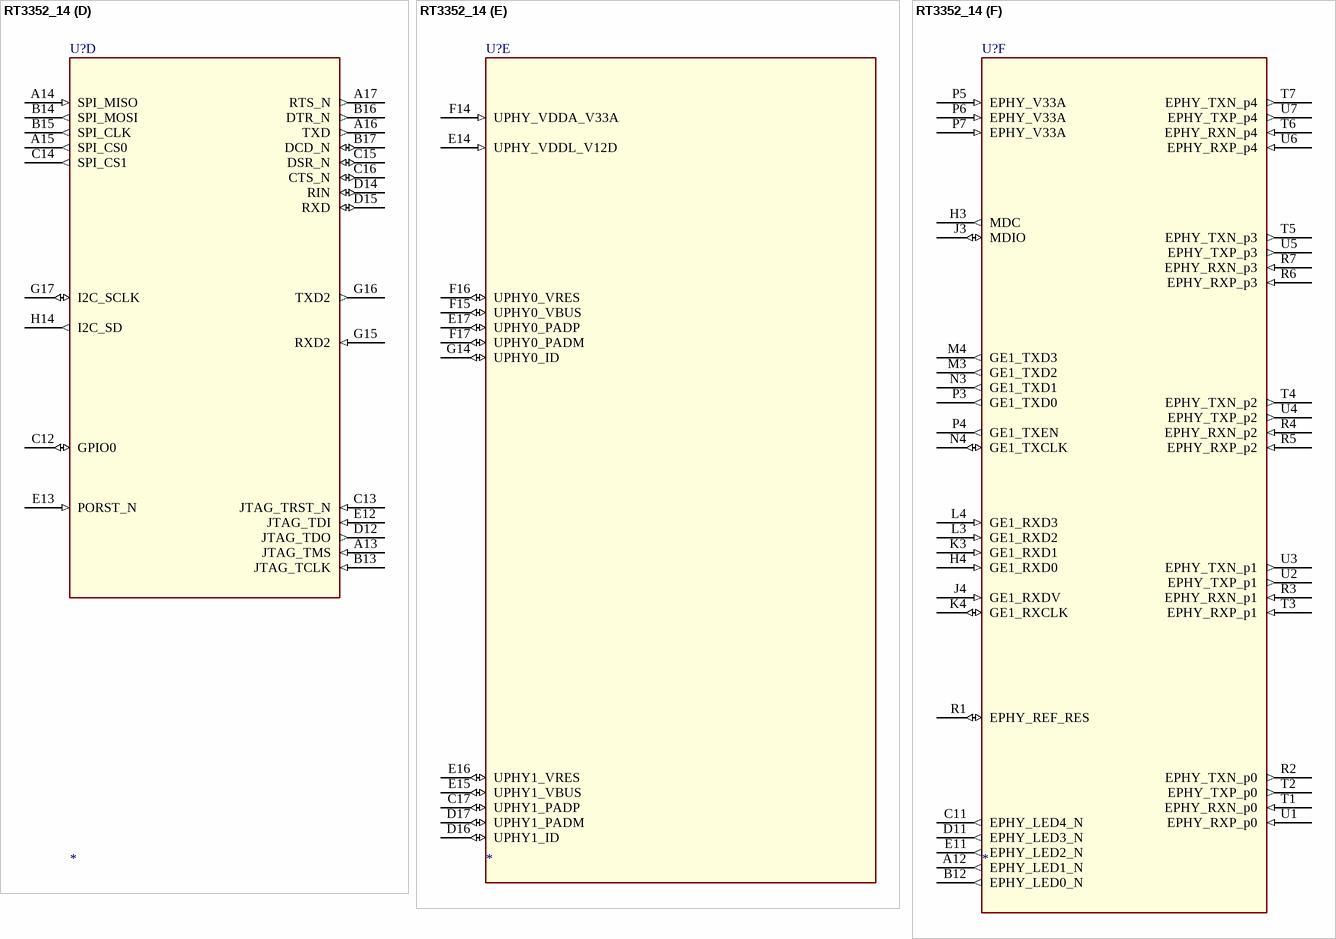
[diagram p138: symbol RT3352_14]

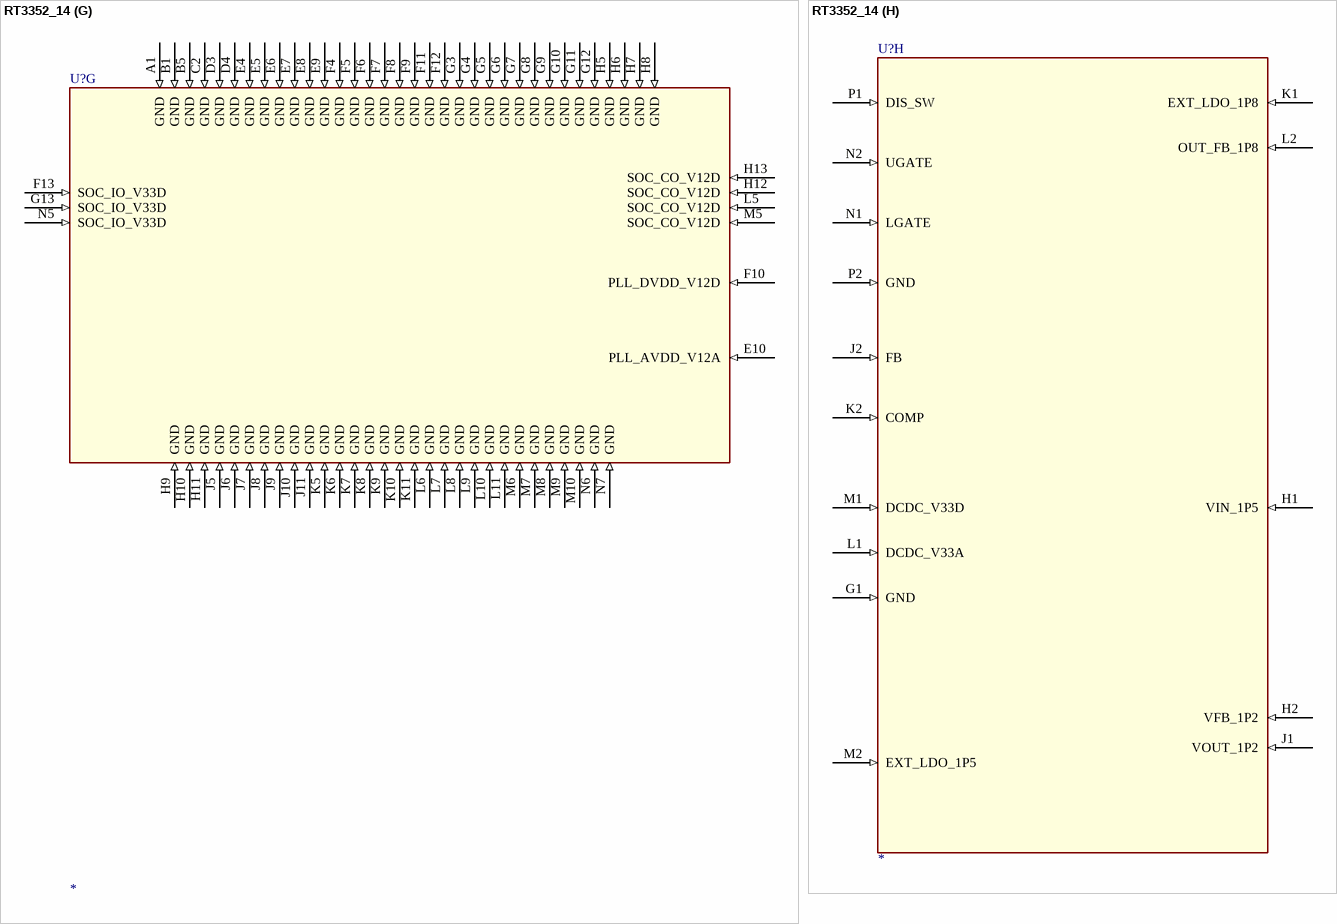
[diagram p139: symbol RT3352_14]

## RT3352_14
designator U?
part A pins: A6 PLL_VC_CAP (in), A7 LDORF_OUT_V12 (out), A8 RF_BB2_V12A (in), A9 ADC_V12 (in), B6 BG_V33A (in), B7 LDORF_IN_VX (in), B8 PLL_X2 (out), B9 PLL_X1 (in), C3 RF0_V12A (in), C4 RF0_IF_V12A (in), C5 VCO_V12A (in), C6 LDOPLL_OUT_V12 (out), C7 BG_RES_12K (in), D5 PLL_V12A (in), D6 RF_BB1_V12A (in), E3 RF1_IF_V12A (in), F3 RF1_V12A (in), G2 RF1_TX_V12A (in)
part B pins: A2 RF0_PA_OUTN (out), A3 RF0_PA_OUTP (out), A4 RF0_2G_INN (in), A5 RF0_2G_INP (in), A10 LNA_PE_G1 (out), A11 ANT_TRNB (out), B2 RF0_PA_V33N (in), B3 RF0_PA_V33P (in), B4 RF0_PA1_V33A (in), B10 LNA_PE_G0 (out), B11 ANT_TRN (out), C1 RF1_2G_INP (in), C8 BASE_TRX_IP (io), C9 BASE_TRX_IN (io), C10 PA_PE_G1 (out), D1 RF1_2G_INN (in), D2 RF1_PA_V33A (in), D7 RF_TSSI_IN (in), D8 BASE_TRX_QP (io), D9 BASE_TRX_QN (io), D10 PA_PE_G0 (out), D13 WLAN_LED_N (out), E1 RF1_PA_OUTP (out), E2 RF1_PA_V33P (in), F1 RF1_PA_OUTN (out), F2 RF1_PA_V33N (in)
part C pins: H15 MD0 (io), H16 MD1 (io), H17 MD2 (io), J12 DDR_IOC_V12D (in), J13 DDR_IOC_V12D (in), J14 MD3 (io), J15 MDQM0 (io), J16 MDQS0 (io), J17 MD6 (io), K12 DDR_IO_V33D (in), K13 DDR_IO_V33D (in), K14 MD8 (io), K15 MD7 (io), K16 MD5 (io), K17 MD4 (io), L12 DDR_IOL_V33D (in), L13 DDR_IOL_V33D (in), L14 MD13 (io), L15 MD10 (io), L16 MD11 (io), L17 MD9 (io), M11 DDR_IO_V33D (in), M12 DDR_IOR_V09D (in), M13 MD15 (io), M14 MD12 (io), M15 MD14 (io), M16 MDQS1 (io), M17 MDQM1 (io), N8 DDR_IO_V33D (in), N9 DDR_IO_V33D (in), N10 DDR_IO_V33D (in), N11 DDR_IO_V33D (in), N12 DDR_IOR_V09D (in), N13 MA0 (io), N14 MA3 (io), N15 MA8 (io), N16 MA10 (io), N17 MA13 (io), P8 MD31 (io), P9 MDQS3 (io), P10 MD22 (io), P11 MDQM2 (io), P12 MD16 (io), P13 MODT (io), P14 MA6 (io), P15 MA4 (io), P16 MA5 (io), P17 MA12 (io), R8 MD30 (io), R9 MD27 (io), R10 MD23 (io), R11 MDQS2 (io), R12 MD17 (io), R13 MCKE (io), R14 MCAS_N (io), R15 MA2 (io), R16 MA7 (io), R17 MA11 (io), T8 MD29 (io), T9 MDQM3 (io), T10 MD24 (io), T11 MD20 (io), T12 MD18 (io), T13 MCK_N (io), T14 MRAS_N (io), T15 MBA0 (io), T16 MA1 (io), T17 MA9 (io), U8 MD28 (io), U9 MD25 (io), U10 MD26 (io), U11 MD21 (io), U12 MD19 (io), U13 MCK_P (io), U14 MWE_N (io), U15 MBA1 (io), U16 MBA2 (io), U17 MCS_N (io)
part D pins: A13 JTAG_TMS (in), A14 SPI_MISO (in), A15 SPI_CS0 (out), A16 TXD (out), A17 RTS_N (out), B13 JTAG_TCLK (in), B14 SPI_MOSI (out), B15 SPI_CLK (out), B16 DTR_N (out), B17 DCD_N (io), C12 GPIO0 (io), C13 JTAG_TRST_N (in), C14 SPI_CS1 (out), C15 DSR_N (io), C16 CTS_N (io), D12 JTAG_TDO (out), D14 RIN (io), D15 RXD (io), E12 JTAG_TDI (in), E13 PORST_N (in), G15 RXD2 (in), G16 TXD2 (out), G17 I2C_SCLK (io), H14 I2C_SD (out)
part E pins: C17 UPHY1_PADP (io), D16 UPHY1_ID (io), D17 UPHY1_PADM (io), E14 UPHY_VDDL_V12D (in), E15 UPHY1_VBUS (io), E16 UPHY1_VRES (io), E17 UPHY0_PADP (io), F14 UPHY_VDDA_V33A (in), F15 UPHY0_VBUS (io), F16 UPHY0_VRES (io), F17 UPHY0_PADM (io), G14 UPHY0_ID (io)
part F pins: A12 EPHY_LED1_N (out), B12 EPHY_LED0_N (out), C11 EPHY_LED4_N (out), D11 EPHY_LED3_N (out), E11 EPHY_LED2_N (out), H3 MDC (out), H4 GE1_RXD0 (in), J3 MDIO (io), J4 GE1_RXDV (in), K3 GE1_RXD1 (in), K4 GE1_RXCLK (io), L3 GE1_RXD2 (in), L4 GE1_RXD3 (in), M3 GE1_TXD2 (out), M4 GE1_TXD3 (out), N3 GE1_TXD1 (out), N4 GE1_TXCLK (io), P3 GE1_TXD0 (out), P4 GE1_TXEN (out), P5 EPHY_V33A (in), P6 EPHY_V33A (in), P7 EPHY_V33A (in), R1 EPHY_REF_RES (io), R2 EPHY_TXN_p0 (out), R3 EPHY_RXN_p1 (in), R4 EPHY_RXN_p2 (in), R5 EPHY_RXP_p2 (in), R6 EPHY_RXP_p3 (in), R7 EPHY_RXN_p3 (in), T1 EPHY_RXN_p0 (in), T2 EPHY_TXP_p0 (out), T3 EPHY_RXP_p1 (in), T4 EPHY_TXN_p2 (out), T5 EPHY_TXN_p3 (out), T6 EPHY_RXN_p4 (in), T7 EPHY_TXN_p4 (out), U1 EPHY_RXP_p0 (in), U2 EPHY_TXP_p1 (out), U3 EPHY_TXN_p1 (out), U4 EPHY_TXP_p2 (out), U5 EPHY_TXP_p3 (out), U6 EPHY_RXP_p4 (in), U7 EPHY_TXP_p4 (out)
part G pins: A1 GND (in), B1 GND (in), B5 GND (in), C2 GND (in), D3 GND (in), D4 GND (in), E4 GND (in), E5 GND (in), E6 GND (in), E7 GND (in), E8 GND (in), E9 GND (in), E10 PLL_AVDD_V12A (in), F4 GND (in), F5 GND (in), F6 GND (in), F7 GND (in), F8 GND (in), F9 GND (in), F10 PLL_DVDD_V12D (in), F11 GND (in), F12 GND (in), F13 SOC_IO_V33D (in), G3 GND (in), G4 GND (in), G5 GND (in), G6 GND (in), G7 GND (in), G8 GND (in), G9 GND (in), G10 GND (in), G11 GND (in), G12 GND (in), G13 SOC_IO_V33D (in), H5 GND (in), H6 GND (in), H7 GND (in), H8 GND (in), H9 GND (in), H10 GND (in), H11 GND (in), H12 SOC_CO_V12D (in), H13 SOC_CO_V12D (in), J5 GND (in), J6 GND (in), J7 GND (in), J8 GND (in), J9 GND (in), J10 GND (in), J11 GND (in), K5 GND (in), K6 GND (in), K7 GND (in), K8 GND (in), K9 GND (in), K10 GND (in), K11 GND (in), L5 SOC_CO_V12D (in), L6 GND (in), L7 GND (in), L8 GND (in), L9 GND (in), L10 GND (in), L11 GND (in), M5 SOC_CO_V12D (in), M6 GND (in), M7 GND (in), M8 GND (in), M9 GND (in), M10 GND (in), N5 SOC_IO_V33D (in), N6 GND (in), N7 GND (in)
part H pins: G1 GND (in), H1 VIN_1P5 (in), H2 VFB_1P2 (in), J1 VOUT_1P2 (in), J2 FB (in), K1 EXT_LDO_1P8 (in), K2 COMP (in), L1 DCDC_V33A (in), L2 OUT_FB_1P8 (in), M1 DCDC_V33D (in), M2 EXT_LDO_1P5 (in), N1 LGATE (in), N2 UGATE (in), P1 DIS_SW (in), P2 GND (in)

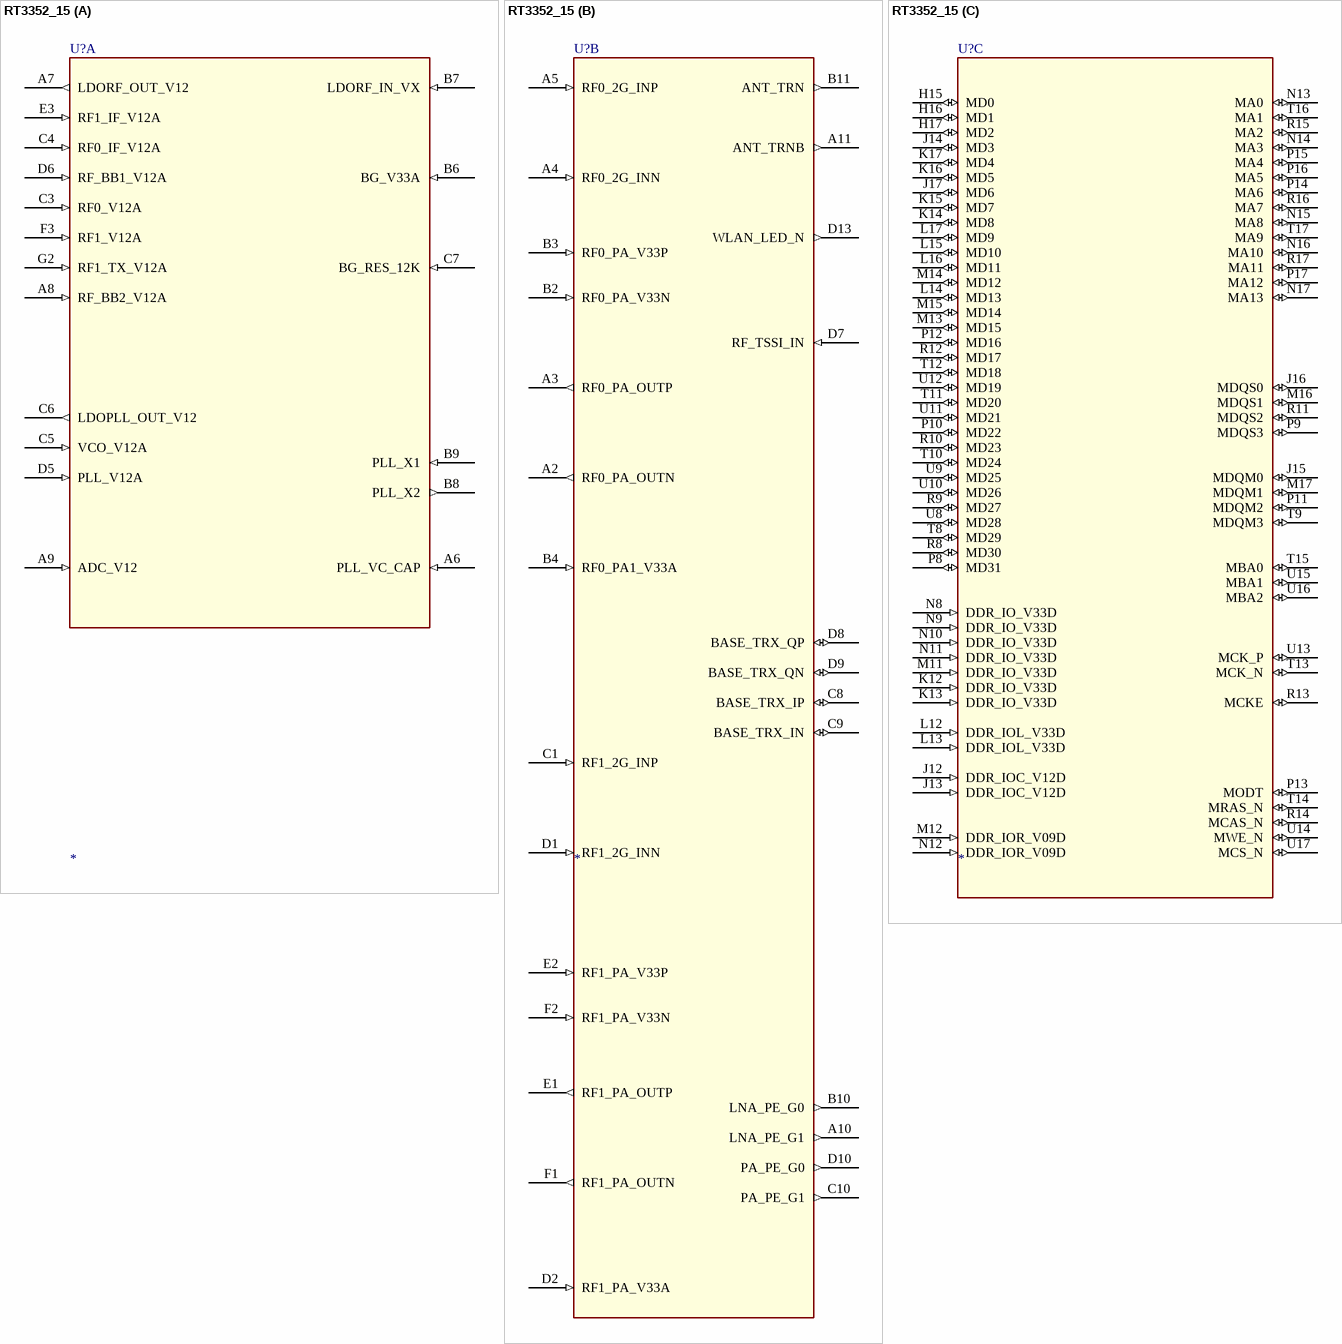
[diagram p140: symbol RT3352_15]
